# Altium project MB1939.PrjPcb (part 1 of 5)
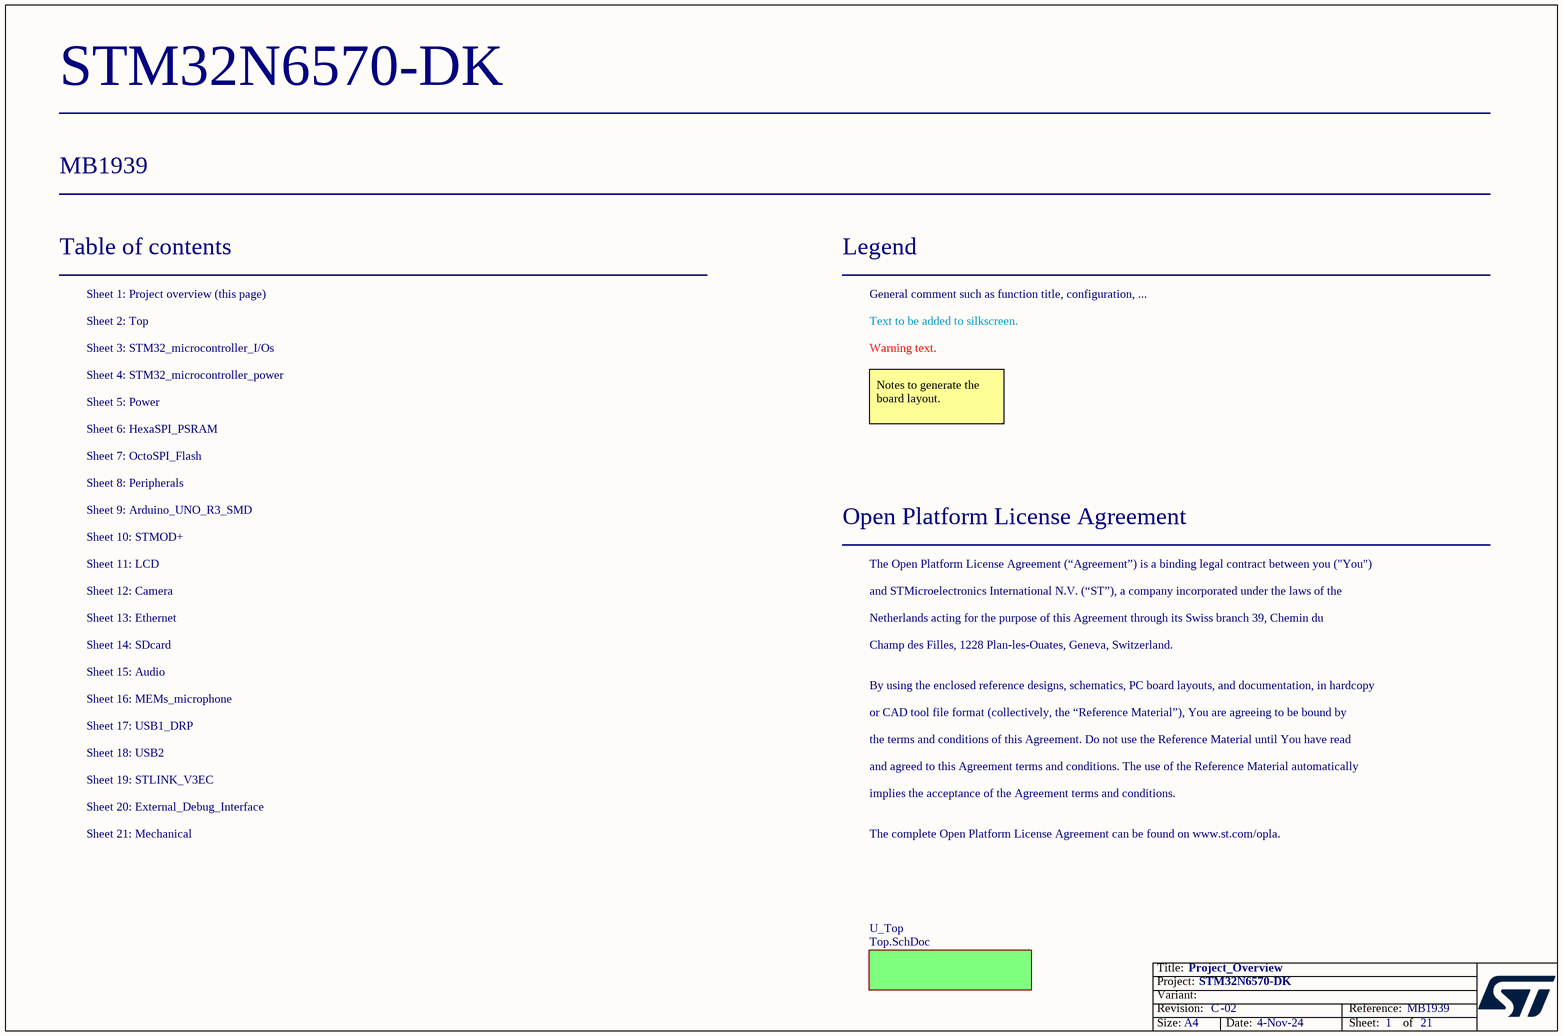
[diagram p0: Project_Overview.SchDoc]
Board_Reference: MB1939; Board_PCB_Revision: C; Board_Name: STM32N6570-DK; Board_Document_Date: 4-Nov-24; Board_Assembly_Revision: 02
21 sheets, 638 parts. Net scope: flat (ports and power ports of the same name join across sheets).
Board file: MB1939.PcbDoc
Sheets:
  Project_Overview.SchDoc
    U_Top = Top.SchDoc
      U_Arduino_UNO_R3_SMD = Arduino_UNO_R3_SMD.SchDoc
      U_Ethernet = Ethernet.SchDoc
      U_External_Debug_Interface = External_Debug_Interface.SchDoc
      U_HexaSPI_PSRAM = HexaSPI_PSRAM.SchDoc
      U_LCD = LCD.SchDoc
      U_Peripherals = Peripherals.SchDoc
      U_MEMs_microphone = MEMs_microphone.SchDoc
      U_OctoSPI_Flash = OctoSPI_Flash.SchDoc
      U_SDcard = SDcard.SchDoc
      U_STLINK_V3EC = STLINK_V3EC.SchDoc
      U_STMOD+ = STMOD+.SchDoc
      U_USB2 = USB2.SchDoc
      U_Mechanical = Mechanical.SchDoc
      U_STM32_microcontroller_power = STM32_microcontroller_power.SchDoc
      U_Audio_Codec = Audio_Codec.SchDoc
      U_USB1_DRP = USB1_DRP.SchDoc
      U_Camera = Camera.SchDoc
      U_Power = Power.SchDoc
      U_STM32_microcontroller_IOs = STM32_microcontroller_IOs.SchDoc

## Sheet Project_Overview.SchDoc: Project_Overview
size A4; Date: Not used; ApprovedBy: Not used; CheckedBy: Not used; Author: Not used; CompanyName: STMicroelectronics; DrawnBy: Not used; Engineer: Not used; Organization: Not used; Address1: Not used; Address2: Not used; Address3: Not used; Address4: Not used; DocumentNumber: Not used; Revision: Not used; SheetNumber: 1; SheetTotal: 21

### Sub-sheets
U_Top = Top.SchDoc: no entries

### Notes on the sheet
- Table of contents
- Sheet 1: Project overview (this page)
- Legend
- General comment such as function title, configuration, ...
- Sheet 2: Top
- Sheet 3: STM32_microcontroller_I/Os
- Sheet 4: STM32_microcontroller_power
- Text to be added to silkscreen.
- Warning text.
- Sheet 5: Power
- Sheet 6: HexaSPI_PSRAM
- Notes to generate the board layout.
- Sheet 7: OctoSPI_Flash
- Sheet 8: Peripherals
- Sheet 9: Arduino_UNO_R3_SMD
- Sheet 10: STMOD+
- Sheet 11: LCD
- Open Platform License Agreement
- The Open Platform License Agreement (“Agreement”) is a binding legal contract between you ("You")
- Sheet 12: Camera
- Sheet 13: Ethernet
- Sheet 14: SDcard
- and STMicroelectronics International N.V. (“ST”), a company incorporated under the laws of the
- Netherlands acting for the purpose of this Agreement through its Swiss branch 39, Chemin du
- Champ des Filles, 1228 Plan-les-Ouates, Geneva, Switzerland.
- Sheet 16: MEMs_microphone
- Sheet 15: Audio
- By using the enclosed reference designs, schematics, PC board layouts, and documentation, in hardcopy
- or CAD tool file format (collectively, the “Reference Material”), You are agreeing to be bound by
- Sheet 17: USB1_DRP
- Sheet 18: USB2
- Sheet 19: STLINK_V3EC
- the terms and conditions of this Agreement. Do not use the Reference Material until You have read
- and agreed to this Agreement terms and conditions. The use of the Reference Material automatically
- Sheet 20: External_Debug_Interface
- Sheet 21: Mechanical
- implies the acceptance of the Agreement terms and conditions.
- The complete Open Platform License Agreement can be found on www.st.com/opla.

## Sheet Top.SchDoc: Top
size A4; Date: Not used; ApprovedBy: Not used; CheckedBy: Not used; Author: Not used; CompanyName: STMicroelectronics; DrawnBy: Not used; Engineer: Not used; Organization: Not used; Address1: Not used; Address2: Not used; Address3: Not used; Address4: Not used; DocumentNumber: Not used; Revision: Not used; SheetNumber: 2; SheetTotal: 21
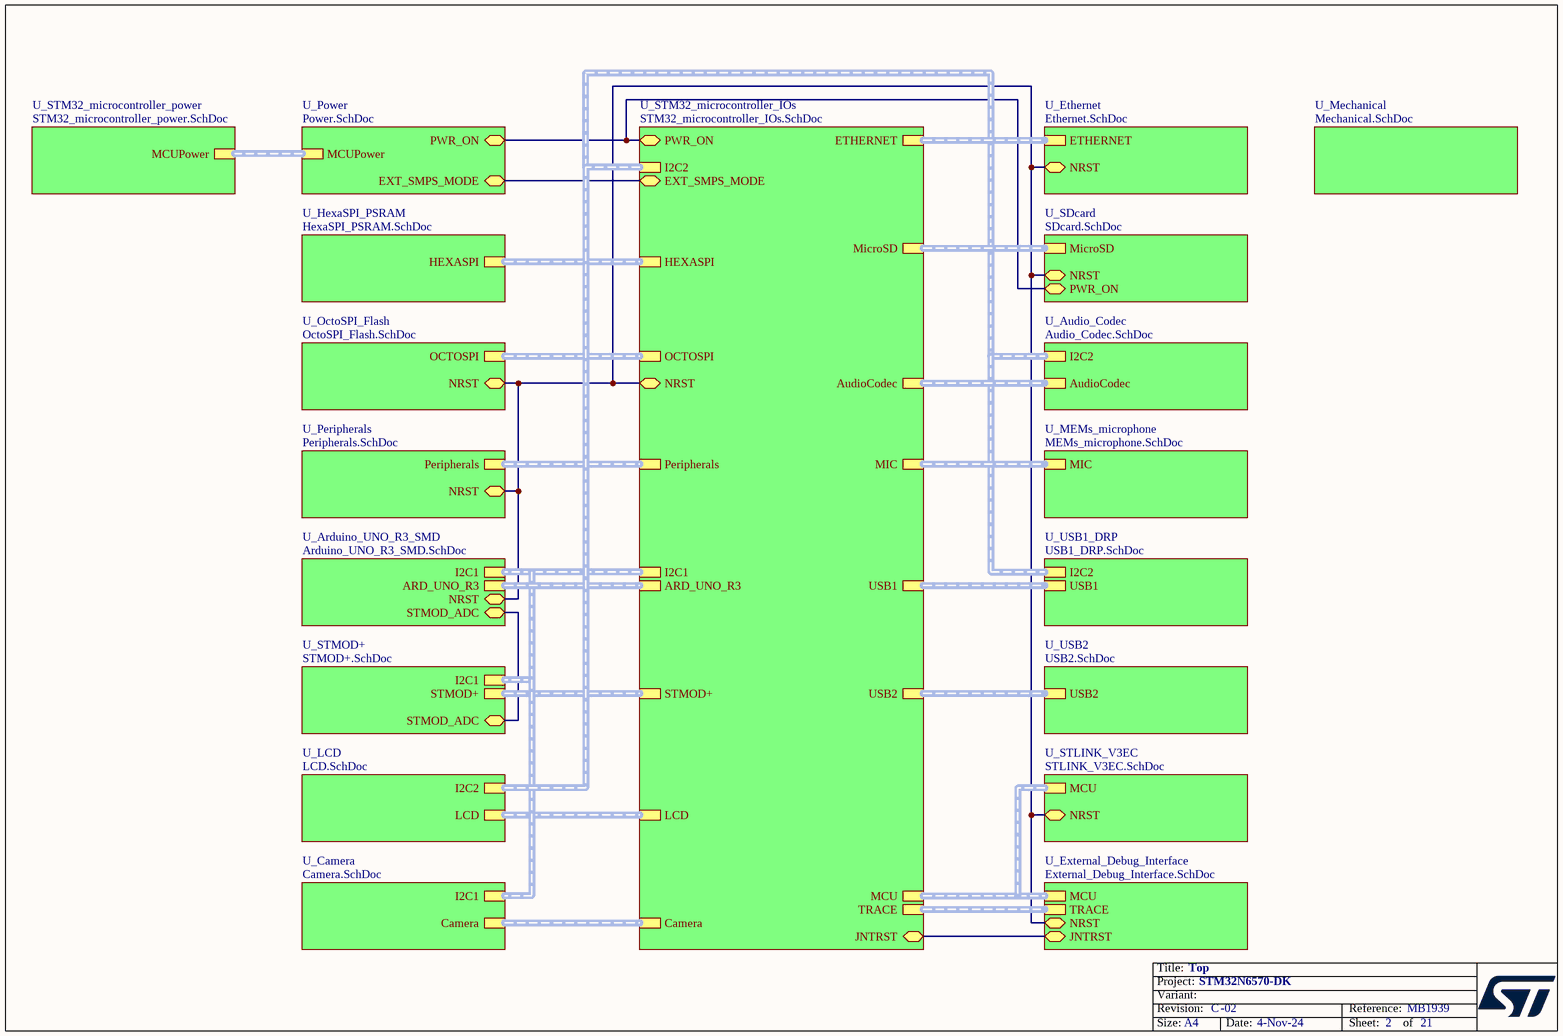
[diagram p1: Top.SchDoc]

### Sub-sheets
U_Arduino_UNO_R3_SMD = Arduino_UNO_R3_SMD.SchDoc: NRST (bidir), STMOD_ADC (bidir), I2C1 (harness I2C1), ARD_UNO_R3 (harness Arduino_UNO_R3)
U_Audio_Codec = Audio_Codec.SchDoc: I2C2 (harness I2C2), AudioCodec (harness AudioCodec)
U_Camera = Camera.SchDoc: Camera (harness Camera), I2C1 (harness I2C1)
U_Ethernet = Ethernet.SchDoc: NRST (bidir), ETHERNET (harness ETHERNET)
U_External_Debug_Interface = External_Debug_Interface.SchDoc: NRST (bidir), MCU (harness MCU), JNTRST (bidir), TRACE (harness TRACE)
U_HexaSPI_PSRAM = HexaSPI_PSRAM.SchDoc: HEXASPI (harness HEXASPI)
U_LCD = LCD.SchDoc: I2C2 (harness I2C2), LCD (harness LCD_RGB)
U_Mechanical = Mechanical.SchDoc: no entries
U_MEMs_microphone = MEMs_microphone.SchDoc: MIC (harness MIC)
U_OctoSPI_Flash = OctoSPI_Flash.SchDoc: NRST (bidir), OCTOSPI (harness OCTOSPI)
U_Peripherals = Peripherals.SchDoc: NRST (bidir), Peripherals (harness Peripherals)
U_Power = Power.SchDoc: PWR_ON (bidir), MCUPower (harness MCUPower), EXT_SMPS_MODE (bidir)
U_SDcard = SDcard.SchDoc: NRST (bidir), PWR_ON (bidir), MicroSD (harness MicroSD_SDIO)
U_STLINK_V3EC = STLINK_V3EC.SchDoc: NRST (bidir), MCU (harness MCU)
U_STM32_microcontroller_IOs = STM32_microcontroller_IOs.SchDoc: ARD_UNO_R3 (harness Arduino_UNO_R3), AudioCodec (harness AudioCodec), Camera (harness Camera), ETHERNET (harness ETHERNET), HEXASPI (harness HEXASPI), Peripherals (harness Peripherals), LCD (harness LCD_RGB), OCTOSPI (harness OCTOSPI), MicroSD (harness MicroSD_SDIO), STMOD+ (harness STMOD+), USB1 (harness USB1), USB2 (harness USB2), NRST (bidir), PWR_ON (bidir), JNTRST (bidir), TRACE (harness TRACE), MCU (harness MCU), I2C2 (harness I2C2), I2C1 (harness I2C1), MIC (harness MIC), EXT_SMPS_MODE (bidir)
U_STM32_microcontroller_power = STM32_microcontroller_power.SchDoc: MCUPower (harness MCUPower)
U_STMOD+ = STMOD+.SchDoc: STMOD_ADC (bidir), STMOD+ (harness STMOD+), I2C1 (harness I2C1)
U_USB1_DRP = USB1_DRP.SchDoc: USB1 (harness USB1), I2C2 (harness I2C2)
U_USB2 = USB2.SchDoc: USB2 (harness USB2)

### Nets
(unnamed): sheet U_Arduino_UNO_R3_SMD/NRST, sheet U_Ethernet/NRST, sheet U_External_Debug_Interface/NRST, sheet U_Peripherals/NRST, sheet U_OctoSPI_Flash/NRST, sheet U_SDcard/NRST, sheet U_STLINK_V3EC/NRST, sheet U_STM32_microcontroller_IOs/NRST
(unnamed): sheet U_Arduino_UNO_R3_SMD/STMOD_ADC, sheet U_STMOD+/STMOD_ADC  [a separate net that carries the same name]
(unnamed): sheet U_External_Debug_Interface/JNTRST, sheet U_STM32_microcontroller_IOs/JNTRST  [a separate net that carries the same name]
(unnamed): sheet U_SDcard/PWR_ON, sheet U_Power/PWR_ON, sheet U_STM32_microcontroller_IOs/PWR_ON  [a separate net that carries the same name]
(unnamed): sheet U_Power/EXT_SMPS_MODE, sheet U_STM32_microcontroller_IOs/EXT_SMPS_MODE  [a separate net that carries the same name]

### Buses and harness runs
harness sheet U_Arduino_UNO_R3_SMD/ARD_UNO_R3 = sheet U_STM32_microcontroller_IOs/ARD_UNO_R3
harness sheet U_Arduino_UNO_R3_SMD/I2C1 = sheet U_Camera/I2C1 = sheet U_STM32_microcontroller_IOs/I2C1 = sheet U_STMOD+/I2C1
harness sheet U_Audio_Codec/AudioCodec = sheet U_STM32_microcontroller_IOs/AudioCodec
harness sheet U_Audio_Codec/I2C2 = sheet U_LCD/I2C2 = sheet U_STM32_microcontroller_IOs/I2C2 = sheet U_USB1_DRP/I2C2
harness sheet U_Camera/Camera = sheet U_STM32_microcontroller_IOs/Camera
harness sheet U_Ethernet/ETHERNET = sheet U_STM32_microcontroller_IOs/ETHERNET
harness sheet U_External_Debug_Interface/MCU = sheet U_STLINK_V3EC/MCU = sheet U_STM32_microcontroller_IOs/MCU
harness sheet U_External_Debug_Interface/TRACE = sheet U_STM32_microcontroller_IOs/TRACE
harness sheet U_HexaSPI_PSRAM/HEXASPI = sheet U_STM32_microcontroller_IOs/HEXASPI
harness sheet U_LCD/LCD = sheet U_STM32_microcontroller_IOs/LCD
harness sheet U_MEMs_microphone/MIC = sheet U_STM32_microcontroller_IOs/MIC
harness sheet U_OctoSPI_Flash/OCTOSPI = sheet U_STM32_microcontroller_IOs/OCTOSPI
harness sheet U_Peripherals/Peripherals = sheet U_STM32_microcontroller_IOs/Peripherals
harness sheet U_Power/MCUPower = sheet U_STM32_microcontroller_power/MCUPower
harness sheet U_SDcard/MicroSD = sheet U_STM32_microcontroller_IOs/MicroSD
harness sheet U_STM32_microcontroller_IOs/STMOD+ = sheet U_STMOD+/STMOD+
harness sheet U_STM32_microcontroller_IOs/USB1 = sheet U_USB1_DRP/USB1
harness sheet U_STM32_microcontroller_IOs/USB2 = sheet U_USB2/USB2

## Sheet Arduino_UNO_R3_SMD.SchDoc: Schematic sheet title to update
size A3; Date: Not used; ApprovedBy: Not used; CheckedBy: Not used; Author: Not used; CompanyName: STMicroelectronics; DrawnBy: Not used; Engineer: Not used; Organization: Not used; Address1: Not used; Address2: Not used; Address3: Not used; Address4: Not used; DocumentNumber: Not used; Revision: 0.4; SheetNumber: 9; SheetTotal: 21
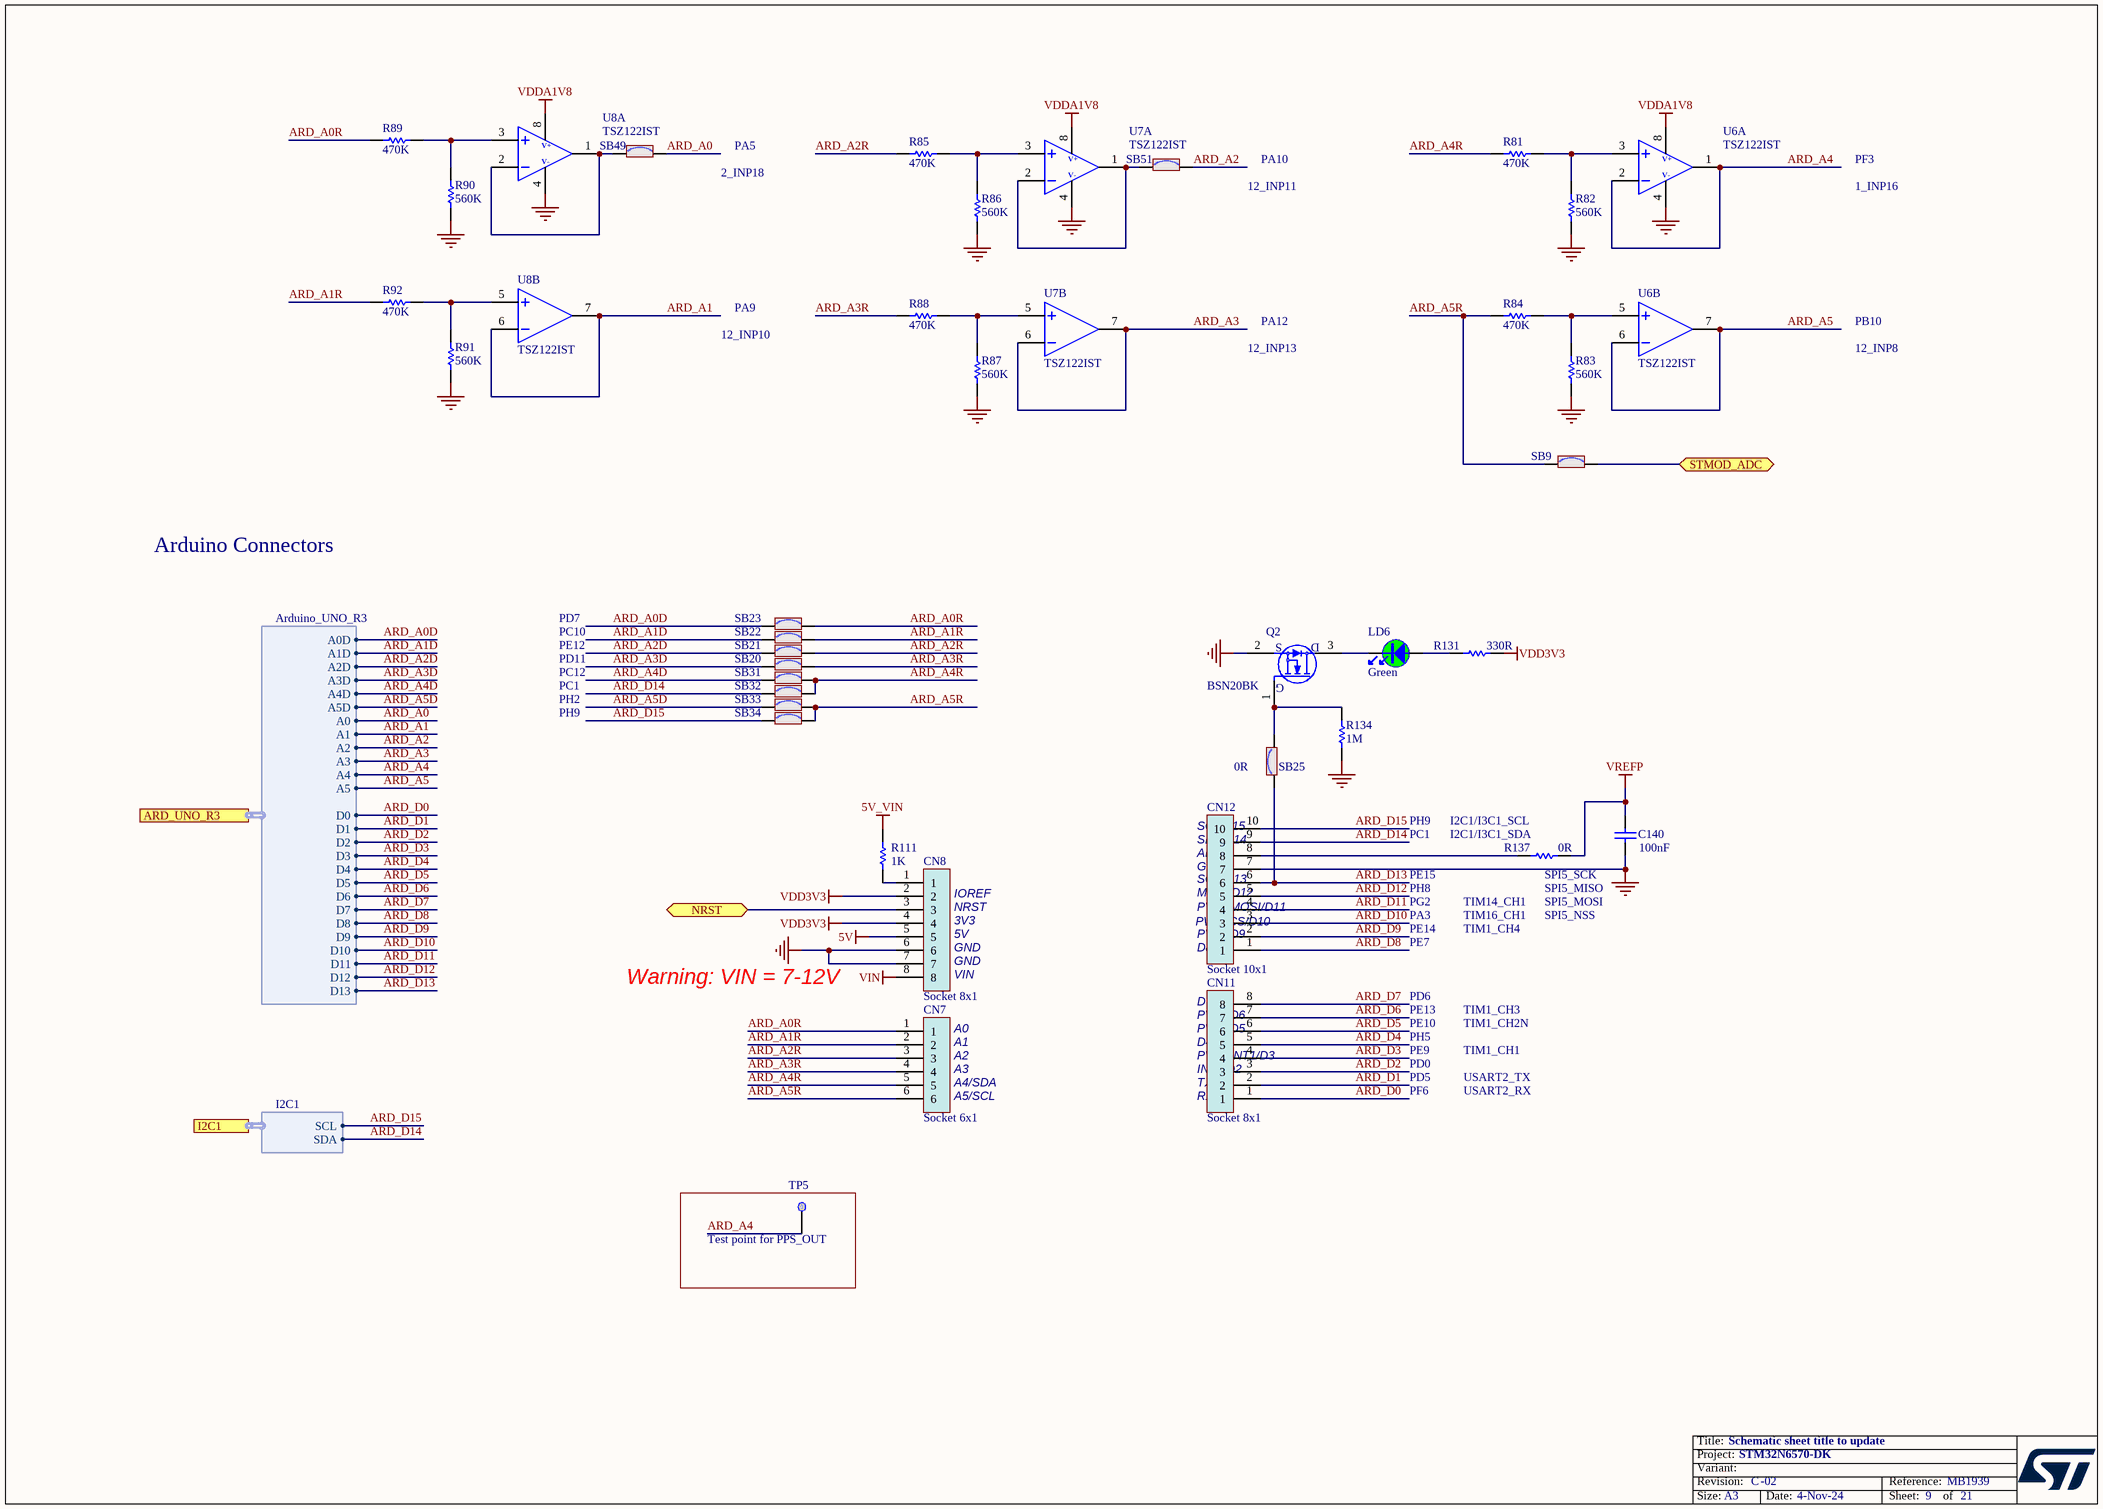
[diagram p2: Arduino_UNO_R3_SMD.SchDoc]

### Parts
C140  value 100nF  [C0402]  (hidden comment: Capacitor)
CN7  Socket 6x1  [CON_SAMTEC_SSW-106-22-X-S-VS]
CN8  Socket 8x1  [CON_SAMTEC_SSW-108-22-X-S-VS]
CN11  Socket 8x1  [CON_SAMTEC_SSW-108-22-X-S-VS]
CN12  Socket 10x1  [CON_SAMTEC_SSW-110-22-X-S-VS]
LD6  value Green  [LED_0603_OSRAM_LG-Q396-PS-35_GREEN_1A2K_H0P4]  (hidden comment: LED_green)
Q2  value BSN20BK  [MOS_SOT23]  (hidden comment: BSN20)
R81  value 470K  [R0402]  (hidden comment: Resistor)
R82  value 560K  [R0402]  (hidden comment: Resistor)
R83  value 560K  [R0402]  (hidden comment: Resistor)
R84  value 470K  [R0402]  (hidden comment: Resistor)
R85  value 470K  [R0402]  (hidden comment: Resistor)
R86  value 560K  [R0402]  (hidden comment: Resistor)
R87  value 560K  [R0402]  (hidden comment: Resistor)
R88  value 470K  [R0402]  (hidden comment: Resistor)
R89  value 470K  [R0402]  (hidden comment: Resistor)
R90  value 560K  [R0402]  (hidden comment: Resistor)
R91  value 560K  [R0402]  (hidden comment: Resistor)
R92  value 470K  [R0402]  (hidden comment: Resistor)
R111  value 1K  [R0402]  (hidden comment: Resistor)
R131  value 330R  [R0402]  (hidden comment: Resistor)
R134  value 1M  [R0402]  (hidden comment: Resistor)
R137  value 0R  [R0402]  (hidden comment: Resistor)
SB9  SB_ON  [SOLDER-BRIDGE_R0603-0R]  (value not drawn)
SB20  SB_ON  [SOLDER-BRIDGE_R0603-0R]  (value not drawn)
SB21  SB_ON  [SOLDER-BRIDGE_R0603-0R]  (value not drawn)
SB22  SB_ON  [SOLDER-BRIDGE_R0603-0R]  (value not drawn)
SB23  SB_ON  [SOLDER-BRIDGE_R0603-0R]  (value not drawn)
SB25  value 0R  [SOLDER-BRIDGE_R0603-0R]  (hidden comment: SB_ON)
SB31  SB_ON  [SOLDER-BRIDGE_R0603-0R]  (value not drawn)
SB32  SB_ON  [SOLDER-BRIDGE_R0603-0R]  (value not drawn)
SB33  SB_ON  [SOLDER-BRIDGE_R0603-0R]  (value not drawn)
SB34  SB_ON  [SOLDER-BRIDGE_R0603-0R]  (value not drawn)
SB49  SB_ON  [SOLDER-BRIDGE_R0603-0R]  (value not drawn)
SB51  SB_ON  [SOLDER-BRIDGE_R0603-0R]  (value not drawn)
TP5  Test Point  [TP_SMD_2MM]  (value not drawn)  (no BOM)
U6  TSZ122IST  [ICC_MINISO8_3X3_P065]  (parts A,B of 2)
U7  TSZ122IST  [ICC_MINISO8_3X3_P065]  (parts A,B of 2)
U8  TSZ122IST  [ICC_MINISO8_3X3_P065]  (parts A,B of 2)

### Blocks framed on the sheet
Test point for PPS_OUT: TP5

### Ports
ARD_UNO_R3 (harness Arduino_UNO_R3), I2C1 (harness I2C1), NRST (bidir), STMOD_ADC (bidir)

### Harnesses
I2C1: SCL, SDA
Arduino_UNO_R3: A0, A1, A2, A3, A4, A5, D0, D1, D2, D3, D4, D5, D6, D7, D8, D9, D10, D11, D12, D13, A0D, A1D, A2D, A3D, A4D, A5D

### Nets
5V: CN8.5
5V_VIN: R111.2
GND: C140.2 CN8.6 CN8.7 CN12.7 Q2.2(S) R82.1 R83.1 R86.1 R87.1 R90.1 R91.1 R134.1 U6.4 U7.4 U8.4
VDD3V3: CN8.2 CN8.4 R131.2
VDDA1V8: U6.8 U7.8 U8.8
VIN: CN8.8
VREFP: C140.1 R137.2
ARD_A0: SB49.2 ; port ARD_UNO_R3.A0
ARD_A0D: SB23.1 ; port ARD_UNO_R3.A0D
ARD_A0R: CN7.1 R89.1 SB23.2
ARD_A1: U8.6 U8.7 ; port ARD_UNO_R3.A1
ARD_A1D: SB22.1 ; port ARD_UNO_R3.A1D
ARD_A1R: CN7.2 R92.1 SB22.2
ARD_A2: SB51.2 ; port ARD_UNO_R3.A2
ARD_A2D: SB21.1 ; port ARD_UNO_R3.A2D
ARD_A2R: CN7.3 R85.1 SB21.2
ARD_A3: U7.6 U7.7 ; port ARD_UNO_R3.A3
ARD_A3D: SB20.1 ; port ARD_UNO_R3.A3D
ARD_A3R: CN7.4 R88.1 SB20.2
ARD_A4: TP5.1 U6.1 U6.2 ; port ARD_UNO_R3.A4
ARD_A4D: SB31.1 ; port ARD_UNO_R3.A4D
ARD_A4R: CN7.5 R81.1 SB31.2 SB32.2
ARD_A5: U6.6 U6.7 ; port ARD_UNO_R3.A5
ARD_A5D: SB33.1 ; port ARD_UNO_R3.A5D
ARD_A5R: CN7.6 R84.1 SB9.1 SB33.2 SB34.2
ARD_D0: CN11.1 ; port ARD_UNO_R3.D0
ARD_D1: CN11.2 ; port ARD_UNO_R3.D1
ARD_D2: CN11.3 ; port ARD_UNO_R3.D2
ARD_D3: CN11.4 ; port ARD_UNO_R3.D3
ARD_D4: CN11.5 ; port ARD_UNO_R3.D4
ARD_D5: CN11.6 ; port ARD_UNO_R3.D5
ARD_D6: CN11.7 ; port ARD_UNO_R3.D6
ARD_D7: CN11.8 ; port ARD_UNO_R3.D7
ARD_D8: CN12.1 ; port ARD_UNO_R3.D8
ARD_D9: CN12.2 ; port ARD_UNO_R3.D9
ARD_D10: CN12.3 ; port ARD_UNO_R3.D10
ARD_D11: CN12.4 ; port ARD_UNO_R3.D11
ARD_D12: CN12.5 ; port ARD_UNO_R3.D12
ARD_D13: CN12.6 SB25.1 ; port ARD_UNO_R3.D13
ARD_D14: CN12.9 SB32.1 ; port I2C1.SDA
ARD_D15: CN12.10 SB34.1 ; port I2C1.SCL
NRST: CN8.3 ; port NRST
STMOD_ADC: SB9.2 ; port STMOD_ADC
NetCN8_1: CN8.1 R111.1
NetCN12_8: CN12.8 R137.1
NetLD6_1: LD6.1 R131.1
NetLD6_2: LD6.2 Q2.3(D)
NetQ2_1: Q2.1(G) R134.2 SB25.2
NetR81_2: R81.2 R82.2 U6.3
NetR83_2: R83.2 R84.2 U6.5
NetR85_2: R85.2 R86.2 U7.3
NetR87_2: R87.2 R88.2 U7.5
NetR89_2: R89.2 R90.2 U8.3
NetR91_2: R91.2 R92.2 U8.5
NetSB49_1: SB49.1 U8.1 U8.2
NetSB51_1: SB51.1 U7.1 U7.2

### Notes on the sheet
- 2_INP18
- PA5
- PA10
- PF3
- 12_INP11
- 1_INP16
- PA9
- 12_INP10
- 12_INP13
- PA12
- PB10
- 12_INP8
- Arduino Connectors
- PC10
- PE12
- PD7
- PD11
- PC12
- PH2
- PH9
- PC1
- (near CN12) SDA/D14
- (near CN12) SCL/D15
- (near CN12) AREF
- (near R137) I2C1/I3C1_SCL
- (near R137) I2C1/I3C1_SDA
- (near CN8) IOREF
- (near CN8) NRST
- (near CN8) 3V3
- (near CN12) PWM/CS/D10
- (near CN12) SCK/D13
- (near CN12) MISO/D12
- (near CN12) GND
- (near CN12) PWM/MOSI/D11
- PG2
- PH8
- PE15
- PA3
- TIM16_CH1
- (near R137) TIM14_CH1
- SPI5_NSS
- (near R137) SPI5_SCK
- SPI5_MOSI
- (near R137) SPI5_MISO
- Warning: VIN = 7-12V
- (near CN8) 5V
- (near CN8) GND
- (near CN8) VIN
- (near CN12) D8
- (near CN12) PWM/D9
- PE7
- PE14
- TIM1_CH4
- (near CN7) A0
- (near CN7) A1
- (near CN7) A2
- (near CN11) D4
- (near CN11) PWM/INT1/D3
- (near CN11) PWM/D5
- (near CN11) PWM/D6
- D7
- PE9
- PE10
- PH5
- PD6
- PE13
- TIM1_CH1
- TIM1_CH2N
- TIM1_CH3
- (near CN7) A3
- (near CN7) A4/SDA
- (near CN7) A5/SCL
- (near CN11) RX/D0
- (near CN11) TX/D1
- (near CN11) INT0/D2
- PD5
- PD0
- PF6
- USART2_RX
- USART2_TX

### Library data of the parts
C140 = MCD-00006: Capacitor, MLCC, 100nF, 16V, X7R, +/-10%, 0402, T=0.5mm; Manufacturer_Part_Number: CC0402KRX7R7BB104; Manufacturer: YAGEO; Part_Preference: Recommended; Partial_Alternate_Internal_Part_Number: MCD-03299; Order_Code_RS: 9402047; Component_Country_Of_Origin: China; ShowFields: YES; ID: 2474
CN7 = MCD-00299: Socket, 6x1, 2.54mm, VR, SMD, T=9.78mm; Part_Type: Connector; Part_Preference: Recommended; Manufacturer: SAMTEC; Manufacturer_Part_Number: SSW-106-22-L-S-VS; Component_Country_Of_Origin: China, Costa Rica, Malaysia, USA, Vietnam; ShowFields: YES; ID: 2569
CN8 CN11 = MCD-00300: Socket, 8x1, 2.54mm, VR, SMD, T=9.78mm; Part_Type: Connector; Part_Preference: Recommended; Manufacturer: SAMTEC; Manufacturer_Part_Number: SSW-108-22-L-S-VS; Component_Country_Of_Origin: China, Costa Rica, Malaysia, USA, Vietnam; ShowFields: YES; ID: 2571
CN12 = MCD-00301: Socket, 10x1, 2.54mm, VR, SMD, T=9.78mm; Part_Type: Connector; Part_Preference: Recommended; Manufacturer: SAMTEC; Manufacturer_Part_Number: SSW-110-22-L-S-VS; Component_Country_Of_Origin: China, Costa Rica, Malaysia, USA, Vietnam; ShowFields: YES; ID: 2566
LD6 = MCD-00588: LED, Green, 2V, 20mA, 0603; Part_Type: Display; Manufacturer_Part_Number: LG Q396-PS-35; Manufacturer: OSRAM OPTO SEMICONDUCTORS; Part_Preference: Recommended; Partial_Alternate_Internal_Part_Number: MCD-02400, MCD-03155, MCD-02901; Component_Country_Of_Origin: Unknown; ShowFields: YES; ID: 3155
Q2 = MCD-01969: Transistor, MOSFET, N-CH, 60V, 265mA, SOT23-3; Part_Preference: Recommended; Manufacturer: NEXPERIA; Order_Code_RS: 136-4845; Component_Country_Of_Origin: China; ShowFields: YES; ID: 4069
R81 R84 R85 R88 R89 R92 = MCD-00483: Resistor, 470K, 0402, +/-1%, 1/16W; Part_Preference: Recommended; Manufacturer: YAGEO; Manufacturer_Part_Number: RC0402FR-07470KL; Component_Country_Of_Origin: China; ShowFields: YES; ID: 2797
R82 R83 R86 R87 R90 R91 = MCD-00495: Resistor, 560K, 0402, +/-1%, 1/16W; Part_Preference: Recommended; Manufacturer: YAGEO; Manufacturer_Part_Number: RC0402FR-07560KL; Component_Country_Of_Origin: China; ShowFields: YES; ID: 2779
R111 = MCD-00061: Resistor, 1K, 0402, +/-1%,1/16W; Manufacturer_Part_Number: RC0402FR-071KL; Manufacturer: YAGEO; Part_Preference: Recommended; Order_Code_RS: 9239235; Component_Country_Of_Origin: China; ShowFields: YES; ID: 2532
R131 = MCD-00062: Resistor, 330R, 0402, +/-1%, 1/16W; Manufacturer_Part_Number: RC0402FR-07330RL; Manufacturer: YAGEO; Part_Preference: Recommended; Order_Code_RS: 9239170; Component_Country_Of_Origin: China; ShowFields: YES; ID: 2529
R134 = MCD-00182: Resistor, 1M, 0402, +/-1%, 1/16W; Manufacturer_Part_Number: RC0402FR-071ML; Manufacturer: YAGEO; BMS_Part_Number: 9131778; Part_Preference: Recommended; Order_Code_RS: 618-6194; Component_Country_Of_Origin: China; ShowFields: YES; ID: 2686
R137 = MCD-00052: Resistor, 0R, 0402, +/-5%, 1/16W; Manufacturer_Part_Number: RC0402JR-070RL; Manufacturer: YAGEO; Part_Preference: Recommended; Order_Code_RS: 9232516RL; Component_Country_Of_Origin: China; ShowFields: YES; ID: 2540
SB9 SB20-SB23 SB25 SB31-SB34 SB49 SB51 = MCD-00071: Resistor, 0R, SB0603, 5%, 0.1W; Manufacturer_Part_Number: RC0603JR-070RL; Manufacturer: YAGEO; Part_Preference: Recommended; Manufacturer_HQ_COO: Unknown; ShowFields: YES; ID: 2521; Order_Code_RS: 199-5647; Component_Country_Of_Origin: China
TP5 = MCD-00177: Test Point, SMD, 2mm; Part_Type: Misc; Part_Preference: Recommended; ShowFields: YES; ID: 2690; Component_Country_Of_Origin: Unknown
U6-U8 = MCD-00325: Operational Amplifier, Single/dual/quad rail-to-rail input/output, 5V5, 400KHz; BMS_Part_Number: 9177443; Part_Type: IC; Part_Preference: Recommended; Manufacturer: STMICROELECTRONICS; Manufacturer_HQ_COO: EU; Component_Country_Of_Origin: Philippines; ShowFields: YES; ID: 2953

## Sheet Ethernet.SchDoc: Ethernet
size A4; Date: 01-DEC-2013; CompanyName: STMicroelectronics; Organization: Microcontrollers Division; Address1: 12, Rue Jules HOROWITZ; Address2: 38019 Grenoble; Address3: FRANCE; DocumentNumber: MB1272; Revision: A-01; SheetNumber: 13; SheetTotal: 21; Project: STM32MP15-DISCO PI
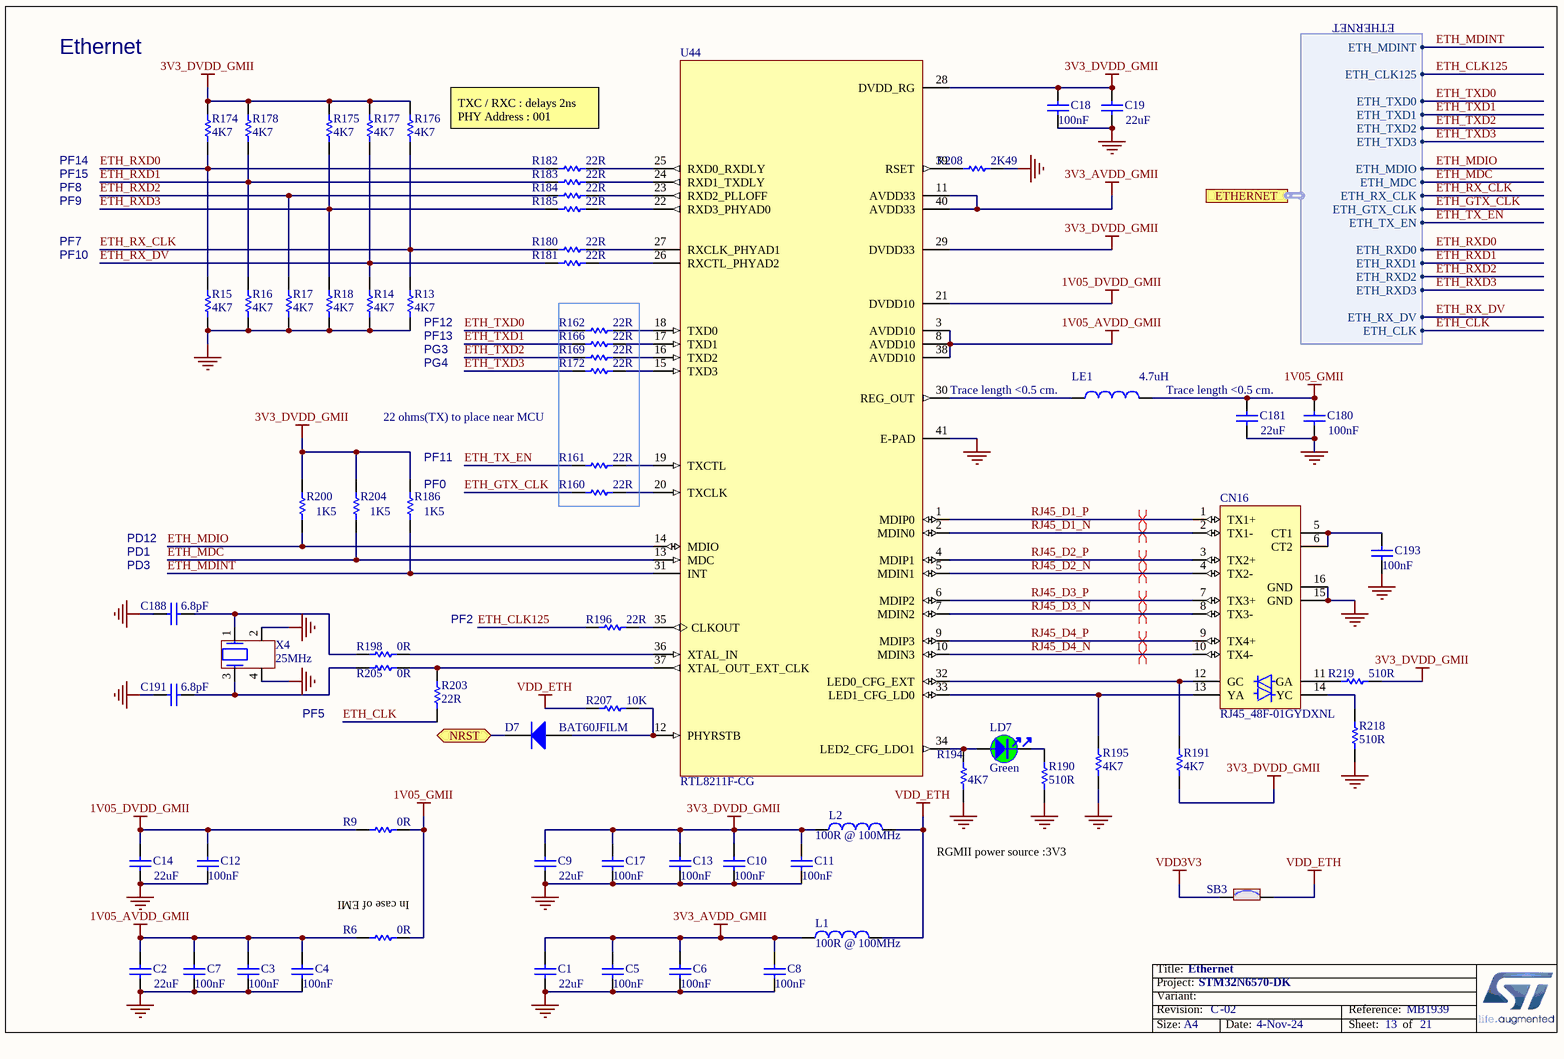
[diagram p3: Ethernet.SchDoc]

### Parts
C1  value 22uF  [C0603]  (hidden comment: Capacitor)
C2  value 22uF  [C0603]  (hidden comment: Capacitor)
C3  value 100nF  [C0402]  (hidden comment: Capacitor)
C4  value 100nF  [C0402]  (hidden comment: Capacitor)
C5  value 100nF  [C0402]  (hidden comment: Capacitor)
C6  value 100nF  [C0402]  (hidden comment: Capacitor)
C7  value 100nF  [C0402]  (hidden comment: Capacitor)
C8  value 100nF  [C0402]  (hidden comment: Capacitor)
C9  value 22uF  [C0603]  (hidden comment: Capacitor)
C10  value 100nF  [C0402]  (hidden comment: Capacitor)
C11  value 100nF  [C0402]  (hidden comment: Capacitor)
C12  value 100nF  [C0402]  (hidden comment: Capacitor)
C13  value 100nF  [C0402]  (hidden comment: Capacitor)
C14  value 22uF  [C0603]  (hidden comment: Capacitor)
C17  value 100nF  [C0402]  (hidden comment: Capacitor)
C18  value 100nF  [C0402]  (hidden comment: Capacitor)
C19  value 22uF  [C0603]  (hidden comment: Capacitor)
C180  value 100nF  [C0402]  (hidden comment: Capacitor)
C181  value 22uF  [C0603]  (hidden comment: Capacitor)
C188  value 6.8pF  [C0402]  (hidden comment: Capacitor)
C191  value 6.8pF  [C0402]  (hidden comment: Capacitor)
C193  value 100nF  [C0402]  (hidden comment: Capacitor)
CN16  value RJ45_48F-01GYDXNL  [CON_RJ45_YD_48F-01GYDXNL_LED-P]  (hidden comment: ​New part for use of led pulled down on pin 13/14 , schematic more lisible.)
D7  BAT60JFILM  [DIO_SOD323]
L1  value 100R @ 100MHz  [FIL_0603_H0P65]  (hidden comment: BEAD)
L2  value 100R @ 100MHz  [FIL_0603_H0P65]  (hidden comment: BEAD)
LD7  value Green  [LED_0603_OSRAM_LG-Q396-PS-35_GREEN_1A2K_H0P4]  (hidden comment: LED_green)
LE1  value 4.7uH  [L1210_LQH]  (hidden comment: Inductor)
R6  value 0R  [R0603]  (hidden comment: Resistor)
R9  value 0R  [R0603]  (hidden comment: Resistor)
R13  value 4K7  [R0402]  (hidden comment: Resistor)
R14  value 4K7  [R0402]  (hidden comment: Resistor)
R15  value 4K7  [R0402]  (hidden comment: Resistor)
R16  value 4K7  [R0402]  (hidden comment: Resistor)
R17  value 4K7  [R0402]  (hidden comment: Resistor)
R18  value 4K7  [R0402]  (hidden comment: Resistor)
R160  value 22R  [R0402]  (hidden comment: Resistor)
R161  value 22R  [R0402]  (hidden comment: Resistor)
R162  value 22R  [R0402]  (hidden comment: Resistor)
R166  value 22R  [R0402]  (hidden comment: Resistor)
R169  value 22R  [R0402]  (hidden comment: Resistor)
R172  value 22R  [R0402]  (hidden comment: Resistor)
R174  value 4K7  [R0402]  (hidden comment: Resistor)
R175  value 4K7  [R0402]  (hidden comment: Resistor)
R176  value 4K7  [R0402]  (hidden comment: Resistor)
R177  value 4K7  [R0402]  (hidden comment: Resistor)
R178  value 4K7  [R0402]  (hidden comment: Resistor)
R180  value 22R  [R0402]  (hidden comment: Resistor)
R181  value 22R  [R0402]  (hidden comment: Resistor)
R182  value 22R  [R0402]  (hidden comment: Resistor)
R183  value 22R  [R0402]  (hidden comment: Resistor)
R184  value 22R  [R0402]  (hidden comment: Resistor)
R185  value 22R  [R0402]  (hidden comment: Resistor)
R186  value 1K5  [R0402]  (hidden comment: Resistor)
R190  value 510R  [R0402]  (hidden comment: Resistor)
R191  value 4K7  [R0402]  (hidden comment: Resistor)
R194  value 4K7  [R0402]  (hidden comment: Resistor)
R195  value 4K7  [R0402]  (hidden comment: Resistor)
R196  value 22R  [R0402]  (hidden comment: Resistor)
R198  value 0R  [R0402]  (hidden comment: Resistor)
R200  value 1K5  [R0402]  (hidden comment: Resistor)
R203  value 22R  [R0402]  (hidden comment: Resistor)
R204  value 1K5  [R0402]  (hidden comment: Resistor)
R205  value 0R  [R0402]  (hidden comment: Resistor)
R207  value 10K  [R0402]  (hidden comment: Resistor)
R208  value 2K49  [R0402]  (hidden comment: Resistor)
R218  value 510R  [R0402]  (hidden comment: Resistor)
R219  value 510R  [R0402]  (hidden comment: Resistor)
SB3  SB_ON  [SOLDER-BRIDGE_R0402-0R]  (value not drawn)
U44  RTL8211F-CG  [ICC_QFN40-EPAD_5X5_P040]
X4  value 25MHz  [CRY_NX3225HA_4P]  (hidden comment: XTAL_4_PINS)

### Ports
ETHERNET (harness ETHERNET), NRST (bidir)

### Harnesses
ETHERNET: ETH_MDINT, ETH_CLK125, ETH_TXD0, ETH_MDIO, ETH_MDC, ETH_RX_CLK, ETH_GTX_CLK, ETH_TX_EN, ETH_RXD0, ETH_RX_DV, ETH_CLK, ETH_TXD1, ETH_TXD2, ETH_TXD3, ETH_RXD1, ETH_RXD2, ETH_RXD3

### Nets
1V05_AVDD_GMII: C2.2 C3.2 C4.2 C7.2 R6.1 U44.3(AVDD10) U44.8(AVDD10) U44.38(AVDD10)
1V05_DVDD_GMII: C12.2 C14.2 R9.1 U44.21(DVDD10)
1V05_GMII: C180.2 C181.2 LE1.2 R6.2 R9.2
3V3_AVDD_GMII: C1.2 C5.2 C6.2 C8.2 L1.1 U44.11(AVDD33) U44.40(AVDD33)
3V3_DVDD_GMII: C9.2 C10.2 C11.2 C13.2 C17.2 C18.2 C19.1 L2.1 R174.2 R175.2 R176.2 R177.2 R178.2 R186.2 R191.1 R200.2 R204.2 R219.2 U44.28(DVDD_RG) U44.29(DVDD33)
GND: C1.1 C2.1 C3.1 C4.1 C5.1 C6.1 C7.1 C8.1 C9.1 C10.1 C11.1 C12.1 C13.1 C14.1 C17.1 C18.1 C19.2 C180.1 C181.1 C188.1 C191.1 C193.1 CN16.15(GND) CN16.16(GND) R13.1 R14.1 R15.1 R16.1 R17.1 R18.1 R190.1 R194.1 R195.1 R208.2 R218.1 U44.41(E-PAD) X4.2 X4.4
VDD3V3: SB3.1
VDD_ETH: L1.2 L2.2 R207.1 SB3.2
ETH_CLK: R203.2 ; port ETHERNET.ETH_CLK
ETH_CLK125: R196.1 ; port ETHERNET.ETH_CLK125
ETH_GTX_CLK: R160.1 ; port ETHERNET.ETH_GTX_CLK
ETH_MDC: R204.1 U44.13(MDC) ; port ETHERNET.ETH_MDC
ETH_MDINT: R186.1 U44.31(INT) ; port ETHERNET.ETH_MDINT
ETH_MDIO: R200.1 U44.14(MDIO) ; port ETHERNET.ETH_MDIO
ETH_RX_CLK: R13.2 R176.1 R180.1 ; port ETHERNET.ETH_RX_CLK
ETH_RX_DV: R14.2 R177.1 R181.1 ; port ETHERNET.ETH_RX_DV
ETH_RXD0: R15.2 R174.1 R182.1 ; port ETHERNET.ETH_RXD0
ETH_RXD1: R16.2 R178.1 R183.1 ; port ETHERNET.ETH_RXD1
ETH_RXD2: R17.2 R184.1 ; port ETHERNET.ETH_RXD2
ETH_RXD3: R18.2 R175.1 R185.1 ; port ETHERNET.ETH_RXD3
ETH_TX_EN: R161.1 ; port ETHERNET.ETH_TX_EN
ETH_TXD0: R162.1 ; port ETHERNET.ETH_TXD0
ETH_TXD1: R166.1 ; port ETHERNET.ETH_TXD1
ETH_TXD2: R169.1 ; port ETHERNET.ETH_TXD2
ETH_TXD3: R172.1 ; port ETHERNET.ETH_TXD3
NRST: D7.2(K) ; port NRST
RJ45_D1_N: CN16.2(TX1-) U44.2(MDIN0)
RJ45_D1_P: CN16.1(TX1+) U44.1(MDIP0)
RJ45_D2_N: CN16.4(TX2-) U44.5(MDIN1)
RJ45_D2_P: CN16.3(TX2+) U44.4(MDIP1)
RJ45_D3_N: CN16.8(TX3-) U44.7(MDIN2)
RJ45_D3_P: CN16.7(TX3+) U44.6(MDIP2)
RJ45_D4_N: CN16.10(TX4-) U44.10(MDIN3)
RJ45_D4_P: CN16.9(TX4+) U44.9(MDIP3)
NetC188_2: C188.2 R198.1 X4.1
NetC191_2: C191.2 R205.1 X4.3
NetC193_2: C193.2 CN16.5(CT1) CN16.6(CT2)
NetCN16_11: CN16.11(GA) R219.1
NetCN16_12: CN16.12(GC) R191.2 U44.32(LED0_CFG_EXT)
NetCN16_13: CN16.13(YA) R195.2 U44.33(LED1_CFG_LD0)
NetCN16_14: CN16.14(YC) R218.2
NetD7_1: D7.1(A) R207.2 U44.12(PHYRSTB)
NetLD7_1: LD7.1 R194.2 U44.34(LED2_CFG_LDO1)
NetLD7_2: LD7.2 R190.2
NetLE1_1: LE1.1 U44.30(REG_OUT)
NetR160_2: R160.2 U44.20(TXCLK)
NetR161_2: R161.2 U44.19(TXCTL)
NetR162_2: R162.2 U44.18(TXD0)
NetR166_2: R166.2 U44.17(TXD1)
NetR169_2: R169.2 U44.16(TXD2)
NetR172_2: R172.2 U44.15(TXD3)
NetR180_2: R180.2 U44.27(RXCLK_PHYAD1)
NetR181_2: R181.2 U44.26(RXCTL_PHYAD2)
NetR182_2: R182.2 U44.25(RXD0_RXDLY)
NetR183_2: R183.2 U44.24(RXD1_TXDLY)
NetR184_2: R184.2 U44.23(RXD2_PLLOFF)
NetR185_2: R185.2 U44.22(RXD3_PHYAD0)
NetR196_2: R196.2 U44.35(CLKOUT)
NetR198_2: R198.2 U44.36(XTAL_IN)
NetR203_1: R203.1 R205.2 U44.37(XTAL_OUT_EXT_CLK)
NetR208_1: R208.1 U44.39(RSET)

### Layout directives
differential pair: RJ45_D1_N, RJ45_D1_P, RJ45_D2_N, RJ45_D2_P, RJ45_D3_N, RJ45_D3_P, RJ45_D4_N, RJ45_D4_P

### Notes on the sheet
- Ethernet
- PF15
- PF14
- TXC / RXC : delays 2ns
  PHY Address : 001
- PF9
- PF8
- PF7
- PF10
- (near R13) PF12
- (near R13) PF13
- (near R13) PG3
- PG4
- 22 ohms(TX) to place near MCU
- (near LE1) Trace length <0.5 cm.
- (near C181) Trace length <0.5 cm.
- (near R186) PF0
- (near R186) PF11
- PD12
- PD1
- (near C188) PD3
- PF2
- PF5
- (near R6) In case of EMI
- RGMII power source :3V3

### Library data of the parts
C1 C2 C9 C14 C19 C181 = MCD-00100: Capacitor, MLCC, 22uF, 6V3, X5R, +/-20%, 0603, T=0.8mm; Manufacturer_Part_Number: GRM188R60J226MEA0J; Manufacturer: MURATA; Part_Preference: Recommended; Component_Country_Of_Origin: Japan°°; ShowFields: YES; ID: 2766
C3-C8 C10-C13 C17 C18 C180 C193 = MCD-00006: as C140 on sheet Arduino_UNO_R3_SMD
C188 C191 = MCD-01781: Capacitor, MLCC, 6.8pF, 50V, NPO, +/-0.1pF, 0402, T=0.5mm; Part_Preference: Recommended; Manufacturer: YAGEO; Manufacturer_Part_Number: CC0402BRNPO9BN6R8; Component_Country_Of_Origin: China; ShowFields: YES; ID: 3881
CN16 = MCD-01129: Connector_RJ45, With Gigabit magnetics Mag and LED, 10pins, 2.54mm, VR, TH, T= 13.84mm; Manufacturer_Part_Number: 48F-01GYDXNL; Manufacturer: YUAN DEAN SCIENTIFIC; Part_Preference: Recommended; Component_Country_Of_Origin: Unknown; ShowFields: YES; ID: 3367
D7 = MCD-00034: Diode, Schottky, 0V53, 1A, 10V, SOD323; Manufacturer: STMICROELECTRONICS; BMS_Part_Number: 9151097; Part_Preference: Recommended; Manufacturer_HQ_COO: EU; Component_Country_Of_Origin: China; ShowFields: YES; ID: 2483; Order_Code_RS: 714-6879
L1 L2 = MCD-00094: Ferrite bead, 100R @ 100MHz, +/-25%, 2000mA, 0R045, 0603, T=0.5mm; Manufacturer_Part_Number: BLM18EG101TN1; Manufacturer: MURATA; Part_Type: Inductor; Part_Preference: Recommended; Order_Code_RS: 1515714; Component_Country_Of_Origin: Japan°°; ShowFields: YES; ID: 2774
LD7 = MCD-00588: as LD6 on sheet Arduino_UNO_R3_SMD
LE1 = MCD-00048: Inductor, 4.7uH, +/-30%, 1A, 180mR, 1210, T=1.7mm; Manufacturer_Part_Number: LQH32PN4R7NN0L; Manufacturer: MURATA; Part_Preference: Recommended; Order_Code_RS: 2470296; Component_Country_Of_Origin: Japan°°; ShowFields: YES; ID: 2544
R6 R9 = MCD-00056: Resistor, 0R, 0603, +/-5%, 1/10W; Manufacturer_Part_Number: RC0603JR-070RL; Manufacturer: YAGEO; Part_Preference: Recommended; Order_Code_RS: 9233130RL; Component_Country_Of_Origin: China; ShowFields: YES; ID: 2536
R13-R18 R174-R178 R191 R194 R195 = MCD-00065: Resistor, 4K7, 0402, +/-1%, 1/16W; Manufacturer_Part_Number: RC0402FR-074K7L; Manufacturer: YAGEO; Part_Preference: Recommended; Partial_Alternate_Internal_Part_Number: MCD-03300; Order_Code_RS: 9239316; Component_Country_Of_Origin: China; ShowFields: YES; ID: 2526
R160-R162 R166 R169 R172 R180-R185 R196 R203 = MCD-00189: Resistor, 22R, 0402, +/-1%, 1/16W; Manufacturer_Part_Number: RC0402FR-0722RL; Manufacturer: YAGEO; Part_Preference: Recommended; Component_Country_Of_Origin: China; ShowFields: YES; ID: 2677
R186 R200 R204 = MCD-00068: Resistor, 1K5, 0402, +/-1%, 1/16W; Manufacturer_Part_Number: RC0402FR-071K5L; Manufacturer: YAGEO; Part_Preference: Recommended; Order_Code_RS: 9239251; Component_Country_Of_Origin: China; ShowFields: YES; ID: 2524
R190 R218 R219 = MCD-00064: Resistor, 510R, 0402, +/-1%, 1/16W; Manufacturer_Part_Number: RC0402FR-07510RL; Manufacturer: YAGEO; Part_Preference: Recommended; Order_Code_RS: 1458804; Component_Country_Of_Origin: China; ShowFields: YES; ID: 2525
R198 R205 = MCD-00052: as R137 on sheet Arduino_UNO_R3_SMD
R207 = MCD-00053: Resistor, 10K, 0402, +/-1%, 1/16W; Manufacturer_Part_Number: RC0402FR-0710KL; Manufacturer: YAGEO; BMS_Part_Number: 9131590; Part_Preference: Recommended; Order_Code_RS: 9239359; Component_Country_Of_Origin: China; ShowFields: YES; ID: 2539
R208 = MCD-00183: Resistor, 2K49, 0402, +/-1%, 1/16W; Manufacturer_Part_Number: RC0402FR-072K49L; Manufacturer: YAGEO; Part_Preference: Recommended; Component_Country_Of_Origin: China; ShowFields: YES; ID: 2687
SB3 = MCD-01618: Resistor, 0R, SB0402, 5%, 0.063W; Manufacturer_Part_Number: RC0402JR-070RL; Manufacturer: YAGEO; Part_Preference: Recommended; Order_Code_RS: 618-5804; Component_Country_Of_Origin: China; ShowFields: YES; ID: 3718
U44 = MCD-01130: ETHERNET Transceiver, 10/100/1000M, QFN40 , SMPS version; Manufacturer: REALTEK; Part_Type: IC; Part_Preference: Recommended; Component_Country_Of_Origin: USA; ShowFields: YES; ID: 3370
X4 = MCD-01463: Crystal, 25MHz, 10pF, +/-20ppm, 50R, 3.2x2.5mm; Part_Type: Crystal_Osc; Manufacturer_Part_Number: NX3225GA-25MHZ-EXS00A-CG06750; Manufacturer: NDK; BMS_Part_Number: 9157035; Part_Preference: Recommended; Component_Country_Of_Origin: Unknown; ShowFields: YES; ID: 3563

## Sheet External_Debug_Interface.SchDoc: External_Debug_Interface
size A4; Date: Not used; ApprovedBy: Not used; CheckedBy: Not used; Author: Not used; CompanyName: STMicroelectronics; DrawnBy: Not used; Engineer: Not used; Organization: Not used; Address1: Not used; Address2: Not used; Address3: Not used; Address4: Not used; DocumentNumber: Not used; Revision: V0.1; SheetNumber: 20; SheetTotal: 21
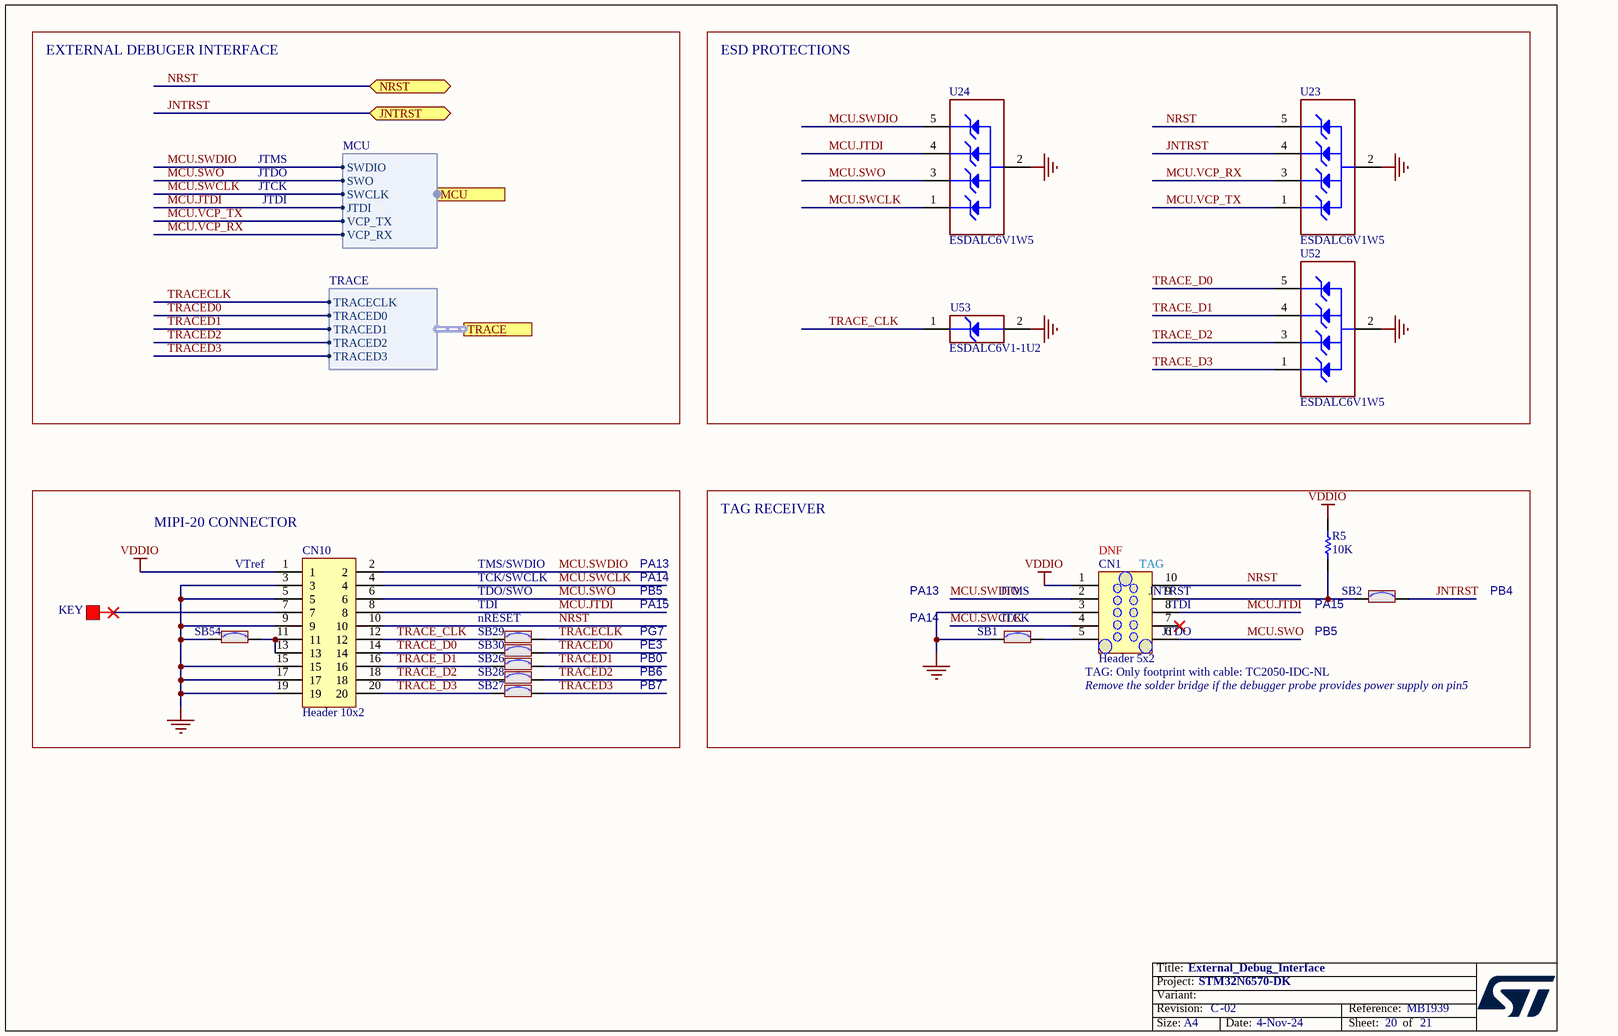
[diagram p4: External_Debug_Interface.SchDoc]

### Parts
CN1  value Header 5x2  [CON_TAG-C_TC2050-IDC-NL]  (hidden comment: Tag-10-C)  (no BOM)
CN10  Header 10x2  [CON_SAMTEC_FTSH-110-01-L-DV]
R5  value 10K  [R0402]  (hidden comment: Resistor)
SB1  SB_ON  [SOLDER-BRIDGE_R0603-0R]  (value not drawn)
SB2  SB_ON  [SOLDER-BRIDGE_R0603-0R]  (value not drawn)
SB26  SB_ON  [SOLDER-BRIDGE_R0402-0R]  (value not drawn)
SB27  SB_ON  [SOLDER-BRIDGE_R0402-0R]  (value not drawn)
SB28  SB_ON  [SOLDER-BRIDGE_R0402-0R]  (value not drawn)
SB29  SB_ON  [SOLDER-BRIDGE_R0402-0R]  (value not drawn)
SB30  SB_ON  [SOLDER-BRIDGE_R0402-0R]  (value not drawn)
SB54  SB_ON  [SOLDER-BRIDGE_R0402-0R]  (value not drawn)
U23  ESDALC6V1W5  [ESD_SOT323-5L]
U24  ESDALC6V1W5  [ESD_SOT323-5L]
U52  ESDALC6V1W5  [ESD_SOT323-5L]
U53  value ESDALC6V1-1U2  [ESD_ST0201]  (hidden comment: ESD-TRANSIL)

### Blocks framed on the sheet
ESD PROTECTIONS: U23 U24 U52 U53
MIPI-20 CONNECTOR: CN10 SB26-SB30 SB54
TAG RECEIVER: CN1 R5 SB1 SB2

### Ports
JNTRST (bidir), MCU (harness MCU), NRST (bidir), TRACE (harness TRACE)

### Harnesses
MCU: SWDIO, SWO, VCP_TX, SWCLK, VCP_RX, JTDI
TRACE: TRACECLK, TRACED2, TRACED0, TRACED3, TRACED1

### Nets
GND: CN1.3 CN10.3 CN10.5 CN10.9 CN10.15 CN10.17 CN10.19 SB1.1 SB54.1 U23.2(GND) U24.2(GND) U52.2(GND) U53.2(GND)
VDDIO: CN1.1 CN10.1 R5.2
JNTRST: SB2.2 U23.4(IO3) ; port JNTRST
MCU.JTDI: CN1.8 CN10.8 U24.4(IO3) ; port MCU.JTDI
MCU.SWCLK: CN1.4 CN10.4 U24.1(IO1) ; port MCU.SWCLK
MCU.SWDIO: CN1.2 CN10.2 U24.5(IO4) ; port MCU.SWDIO
MCU.SWO: CN1.6 CN10.6 U24.3(IO2) ; port MCU.SWO
MCU.VCP_RX: U23.3(IO2) ; port MCU.VCP_RX
MCU.VCP_TX: U23.1(IO1) ; port MCU.VCP_TX
NRST: CN1.10 CN10.10 U23.5(IO4) ; port NRST
TRACE_CLK: CN10.12 SB29.1 U53.1(IO1)
TRACE_D0: CN10.14 SB30.1 U52.5(IO4)
TRACE_D1: CN10.16 SB26.1 U52.4(IO3)
TRACE_D2: CN10.18 SB28.1 U52.3(IO2)
TRACE_D3: CN10.20 SB27.1 U52.1(IO1)
TRACECLK: SB29.2 ; port TRACE.TRACECLK  [project net PG7]
TRACED0: SB30.2 ; port TRACE.TRACED0  [project net PE3]
TRACED1: SB26.2 ; port TRACE.TRACED1  [project net PB0]
TRACED2: SB28.2 ; port TRACE.TRACED2  [project net PB6]
TRACED3: SB27.2 ; port TRACE.TRACED3  [project net PB7]
NetCN1_5: CN1.5 SB1.2
NetCN1_9: CN1.9 R5.1 SB2.1
NetCN10_11: CN10.11 CN10.13 SB54.2

Not connected (* = marked no-connect by the designer): CN1 7*; CN10 7*

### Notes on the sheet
- EXTERNAL DEBUGER INTERFACE
- JTMS
- JTDO
- JTCK
- JTDI
- (near CN10) VTref
- TMS/SWDIO
- TCK/SWCLK
- PA13
- PA14
- (near CN1) DNF
- (near CN1) TAG
- KEY
- TDO/SWO
- TDI
- (near SB29) nRESET
- PG7
- PE3
- PA15
- PB5
- (near SB1) JTCK
- (near CN1) JTDO
- (near CN1) JTDI
- (near CN1) JNTRST
- PB4
- PB6
- PB0
- PB7
- (near CN1) TAG: Only footprint with cable: TC2050-IDC-NL
- (near CN1) Remove the solder bridge if the debugger probe provides power supply on pin5

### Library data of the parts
CN1 = MCD-00031: Header_Plug-of-nails, 5x2, 1.27mm, No legs; Part_Type: Connector; Part_Preference: Recommended; ShowFields: YES; ID: 2486
CN10 = MCD-00557: Header, 10x2, 1.27mm, VR, SMD, T=3.05mm; BMS_Part_Number: 9183690; Part_Type: Connector; Part_Preference: Recommended; Manufacturer: SAMTEC; Manufacturer_Part_Number: FTSH-110-01-L-DV; Partial_Alternate_Internal_Part_Number: MCD-03996; Order_Code_RS: 767-6774; Component_Country_Of_Origin: China, Costa Rica, Malaysia, USA, Vietnam; ShowFields: YES; ID: 3188
R5 = MCD-00053: as R207 on sheet Ethernet
SB1 SB2 = MCD-00071: Resistor, 0R, SB0603, 5%, 0.1W; Part_Preference: Recommended; Manufacturer: YAGEO; Manufacturer_Part_Number: RC0603JR-070RL; Manufacturer_HQ_COO: Unknown; ShowFields: YES; ID: 2521; Order_Code_RS: 199-5647; Component_Country_Of_Origin: China
SB26-SB30 SB54 = MCD-01618: Resistor, 0R, SB0402, 5%, 0.063W; Part_Preference: Recommended; Manufacturer: YAGEO; Manufacturer_Part_Number: RC0402JR-070RL; ShowFields: YES; ID: 3718; Order_Code_RS: 618-5804; Component_Country_Of_Origin: China
U23 U24 U52 = MCD-00136: Diode, ESD Transil, 3V, 1uA, 7V2, SOT323-5; BMS_Part_Number: 9151112; Part_Preference: Recommended; Manufacturer: STMICROELECTRONICS; Manufacturer_HQ_COO: EU; Component_Country_Of_Origin: China; Order_Code_RS: 178-7373; ShowFields: YES; ID: 2731
U53 = MCD-00170: Diode, ESD TVS, 3V, 100nA, 8V, ST0201; BMS_Part_Number: 9151132; Part_Preference: Recommended; Manufacturer: STMICROELECTRONICS; Manufacturer_HQ_COO: EU; Component_Country_Of_Origin: China; ShowFields: YES; ID: 2696; Order_Code_RS: 795-8404

## Sheet HexaSPI_PSRAM.SchDoc: HexaSPI_PSRAM
size A4; Date: Not used; ApprovedBy: Not used; CheckedBy: Not used; Author: Not used; CompanyName: STMicroelectronics; DrawnBy: Not used; Engineer: Not used; Organization: Not used; Address1: Not used; Address2: Not used; Address3: Not used; Address4: Not used; DocumentNumber: Not used; Revision: Not used; SheetNumber: 6; SheetTotal: 21
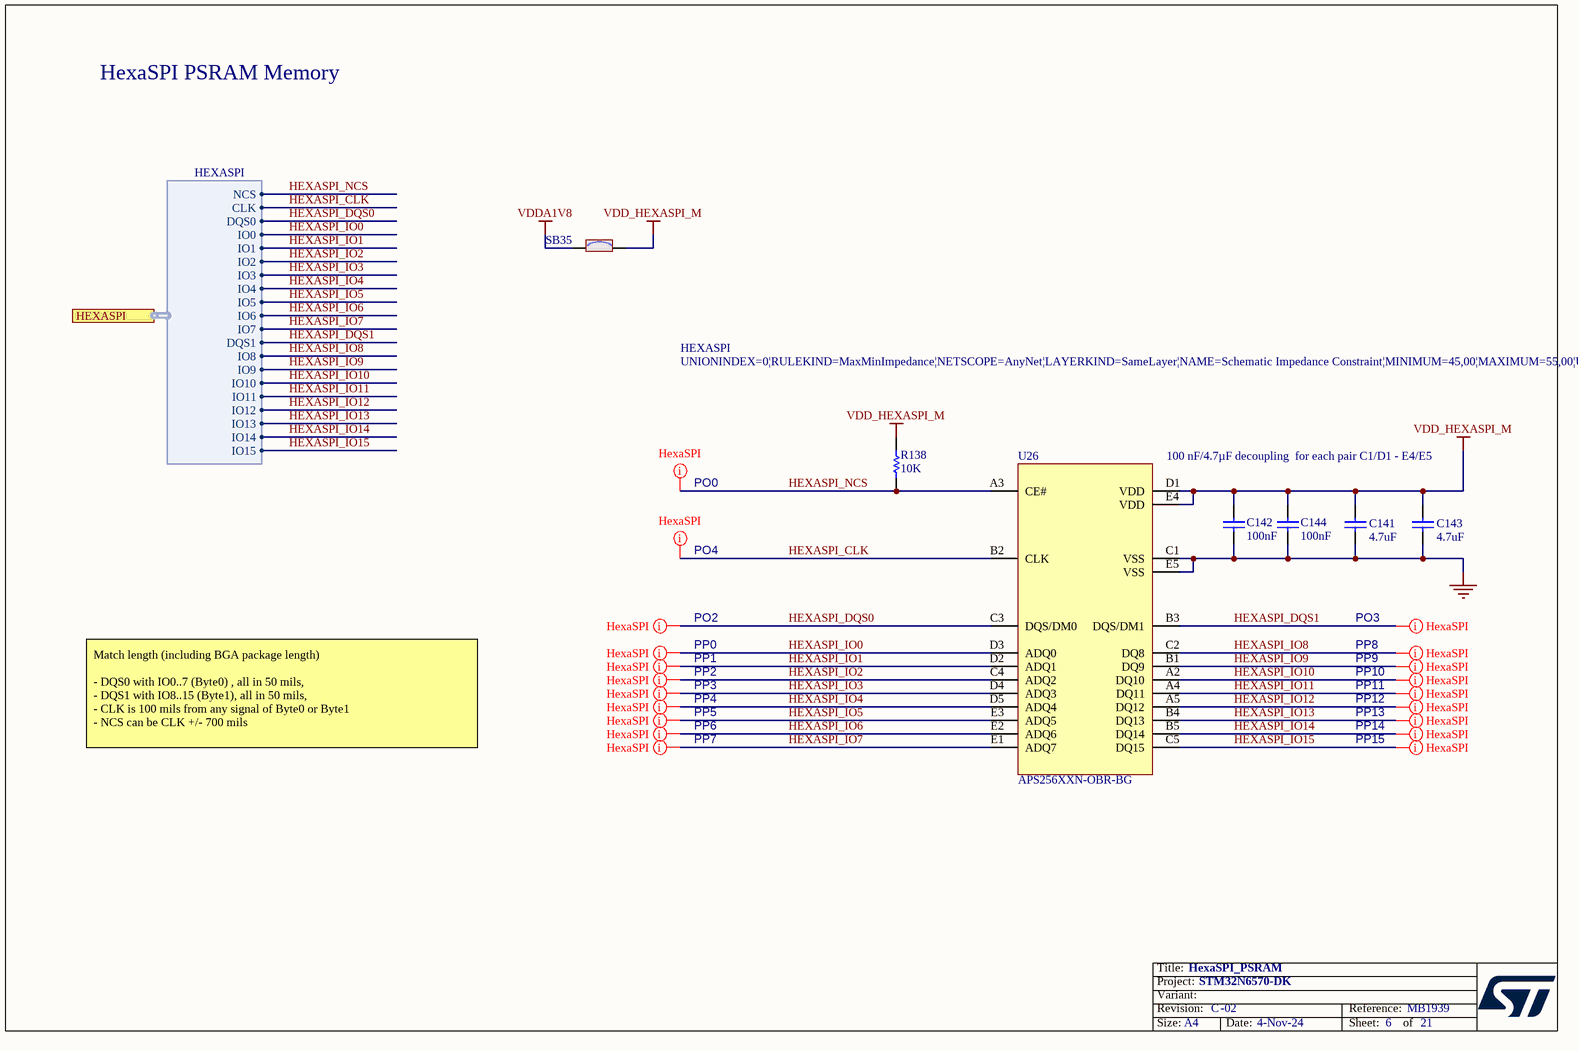
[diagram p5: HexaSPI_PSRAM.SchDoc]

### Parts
C141  value 4.7uF  [C0603]  (hidden comment: Capacitor)
C142  value 100nF  [C0402]  (hidden comment: Capacitor)
C143  value 4.7uF  [C0603]  (hidden comment: Capacitor)
C144  value 100nF  [C0402]  (hidden comment: Capacitor)
R138  value 10K  [R0402]  (hidden comment: Resistor)
SB35  SB_ON  [SOLDER-BRIDGE_R0402-0R]  (value not drawn)
U26  APS256XXN-OBR-BG  [ICC_BGA24_5X5-BALL-ARRAY_6X8_P1]

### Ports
HEXASPI (harness HEXASPI)

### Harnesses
HEXASPI: IO1, IO0, DQS0, NCS, IO2, IO3, IO5, IO4, IO6, IO7, CLK, DQS1, IO8, IO9, IO10, IO11, IO12, IO13, IO14, IO15

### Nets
GND: C141.1 C142.1 C143.1 C144.1 U26.C1(VSS) U26.E5(VSS)
VDD_HEXASPI_M: C141.2 C142.2 C143.2 C144.2 R138.2 SB35.2 U26.D1(VDD) U26.E4(VDD)
VDDA1V8: SB35.1
HEXASPI_CLK: U26.B2(CLK) ; port HEXASPI.CLK
HEXASPI_DQS0: U26.C3(DQS/DM0) ; port HEXASPI.DQS0
HEXASPI_DQS1: U26.B3(DQS/DM1) ; port HEXASPI.DQS1
HEXASPI_IO0: U26.D3(ADQ0) ; port HEXASPI.IO0
HEXASPI_IO1: U26.D2(ADQ1) ; port HEXASPI.IO1
HEXASPI_IO2: U26.C4(ADQ2) ; port HEXASPI.IO2
HEXASPI_IO3: U26.D4(ADQ3) ; port HEXASPI.IO3
HEXASPI_IO4: U26.D5(ADQ4) ; port HEXASPI.IO4
HEXASPI_IO5: U26.E3(ADQ5) ; port HEXASPI.IO5
HEXASPI_IO6: U26.E2(ADQ6) ; port HEXASPI.IO6
HEXASPI_IO7: U26.E1(ADQ7) ; port HEXASPI.IO7
HEXASPI_IO8: U26.C2(DQ8) ; port HEXASPI.IO8
HEXASPI_IO9: U26.B1(DQ9) ; port HEXASPI.IO9
HEXASPI_IO10: U26.A2(DQ10) ; port HEXASPI.IO10
HEXASPI_IO11: U26.A4(DQ11) ; port HEXASPI.IO11
HEXASPI_IO12: U26.A5(DQ12) ; port HEXASPI.IO12
HEXASPI_IO13: U26.B4(DQ13) ; port HEXASPI.IO13
HEXASPI_IO14: U26.B5(DQ14) ; port HEXASPI.IO14
HEXASPI_IO15: U26.C5(DQ15) ; port HEXASPI.IO15
HEXASPI_NCS: R138.1 U26.A3(CE#) ; port HEXASPI.NCS

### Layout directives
rule Matched Net Lengths [Tolerance = 1000mil]; net class HEXASPI; rule Impedance Constraint [Min = 50.00    Max = 60.00    ]; rule Routing Layers [TopLayer - Enabled BottomLayer - Disabled]: HEXASPI_NCS
rule Matched Net Lengths [Tolerance = 20mil]; net class HEXASPI; rule Impedance Constraint [Min = 45.00    Max = 55.00    ]; rule Routing Layers [TopLayer - Enabled BottomLayer - Disabled]: HEXASPI_CLK, HEXASPI_DQS1, HEXASPI_IO0, HEXASPI_IO1, HEXASPI_IO2, HEXASPI_IO3, HEXASPI_IO4, HEXASPI_IO5, HEXASPI_IO6, HEXASPI_IO7, HEXASPI_IO8, HEXASPI_IO9, HEXASPI_IO10, HEXASPI_IO11, HEXASPI_IO12, HEXASPI_IO13, HEXASPI_IO14, HEXASPI_IO15
rule Matched Net Lengths [Tolerance = 20mil]; net class HEXASPI; rule Impedance Constraint [Min = 50.00    Max = 60.00    ]; rule Routing Layers [TopLayer - Enabled BottomLayer - Disabled]: HEXASPI_DQS0

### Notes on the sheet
- HexaSPI PSRAM Memory
- PO0
- (near U26) 100 nF/4.7µF decoupling  for each pair C1/D1 - E4/E5
- PO4
- PO2
- PP0
- PO3
- PP8
- PP1
- PP2
- PP3
- PP4
- PP5
- PP9
- PP10
- PP11
- PP12
- PP13
- Match length (including BGA package length)
  - DQS0 with IO0..7 (Byte0) , all in 50 mils,
  - DQS1 with IO8..15 (Byte1), all in 50 mils,
  - CLK is 100 mils from any signal of Byte0 or Byte1
  - NCS can be CLK +/- 700 mils
- PP6
- PP7
- PP14
- PP15
- Title:
- Project:
- Size:
- Revision:
- Variant:
- A4
- -
- Date:
- Reference:
- Sheet:
- of

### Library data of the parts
C141 C143 = MCD-00009: Capacitor, MLCC, 4.7uF, 16V, X5R, +/-10%, 0603, T=0.8mm; Manufacturer_Part_Number: CC0603KRX5R7BB475; Manufacturer: YAGEO; Part_Preference: Recommended; Partial_Alternate_Internal_Part_Number: MCD-03565; Component_Country_Of_Origin: China; ShowFields: YES; ID: 2471; Alternate_EMS: A
C142 C144 = MCD-00006: as C140 on sheet Arduino_UNO_R3_SMD
R138 = MCD-00053: as R207 on sheet Ethernet
SB35 = MCD-01618: as SB3 on sheet Ethernet
U26 = MCD-02129: Memory, DDR PSRAM, 1V8, 256Mbit, 200MHz, BGA-24; Part_Type: IC; Manufacturer: AP MEMORY TECHNOLOGY CORP.; Part_Preference: Recommended; Component_Country_Of_Origin: Taiwan; ShowFields: YES; ID: 4229

## Sheet LCD.SchDoc: LCD & Camera connectors
size A4; Date: Not used; ApprovedBy: Not used; CheckedBy: Not used; Author: Not used; CompanyName: STMicroelectronics; DrawnBy: Not used; Engineer: Not used; Organization: Not used; Address1: Not used; Address2: Not used; Address3: Not used; Address4: Not used; DocumentNumber: Not used; Revision: Not used; SheetNumber: 11; SheetTotal: 21
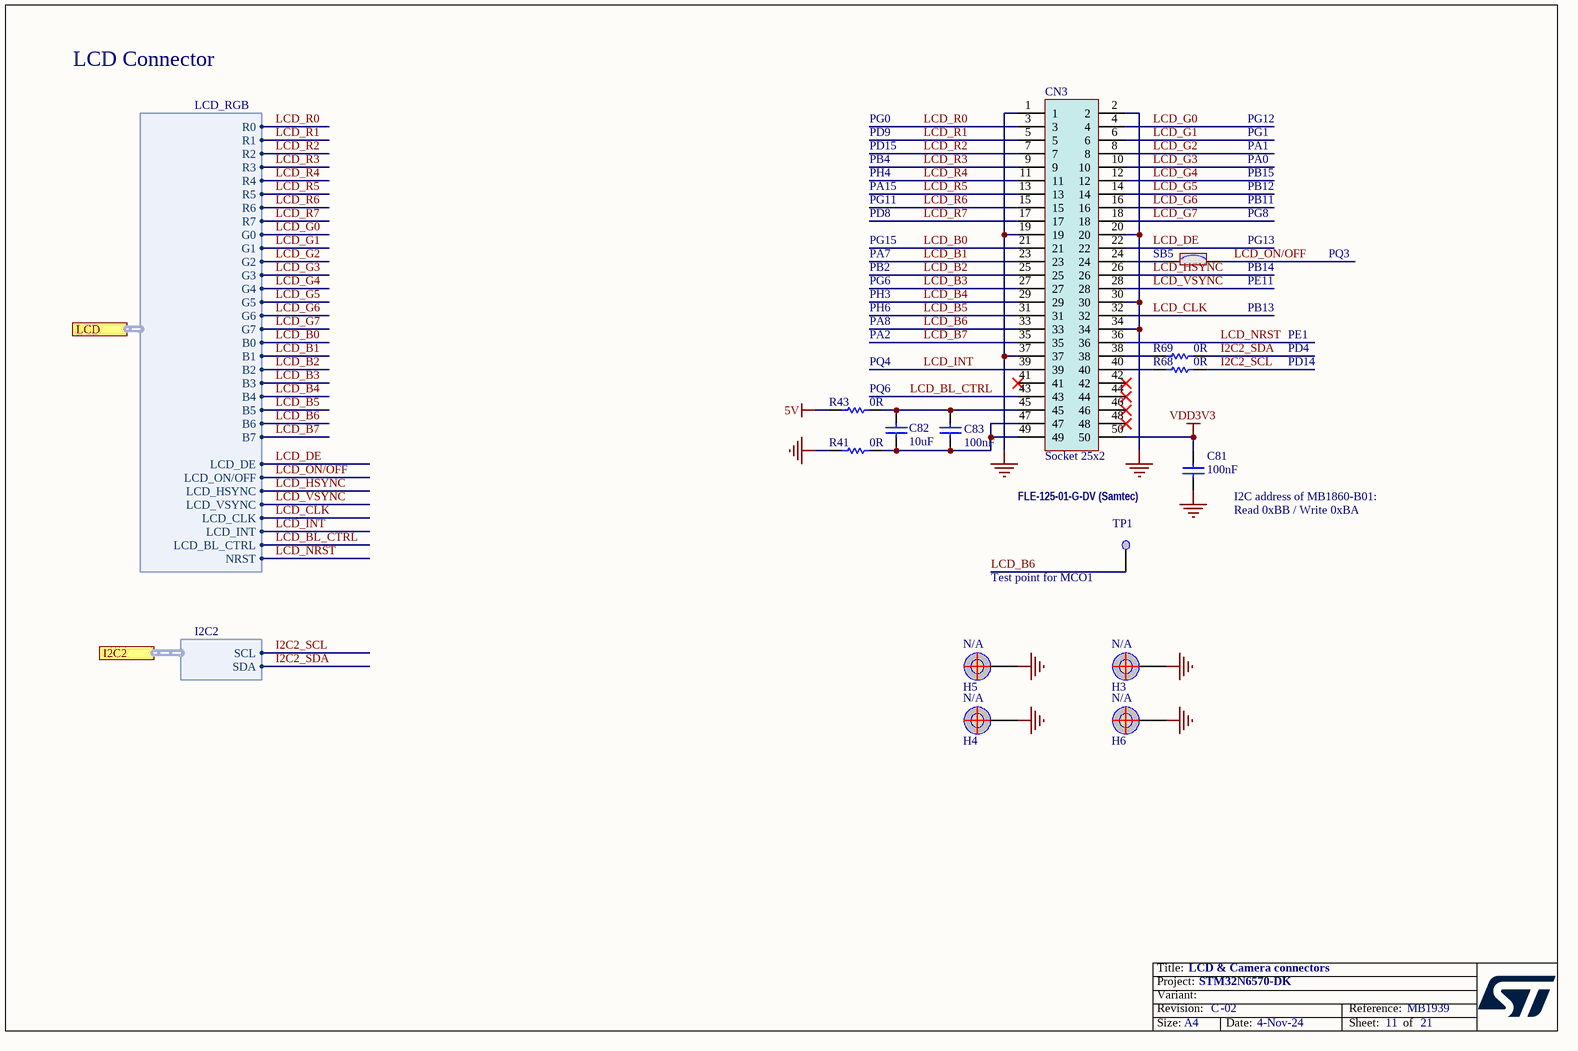
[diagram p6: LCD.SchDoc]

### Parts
C81  value 100nF  [C0402]  (hidden comment: Capacitor)
C82  value 10uF  [C0805]  (hidden comment: Capacitor)
C83  value 100nF  [C0402]  (hidden comment: Capacitor)
CN3  Socket 25x2  [CON_SAMTEC_FLE-125-01-G-DV]
H3  POSITION HOLE  [PTH_450_900]  (value not drawn)  (no BOM)
H4  POSITION HOLE  [PTH_450_900]  (value not drawn)  (no BOM)
H5  POSITION HOLE  [PTH_450_900]  (value not drawn)  (no BOM)
H6  POSITION HOLE  [PTH_450_900]  (value not drawn)  (no BOM)
R41  value 0R  [R0603]  (hidden comment: Resistor)
R43  value 0R  [R0603]  (hidden comment: Resistor)
R68  value 0R  [R0402]  (hidden comment: Resistor)
R69  value 0R  [R0402]  (hidden comment: Resistor)
SB5  SB_ON  [SOLDER-BRIDGE_R0603-0R]  (value not drawn)
TP1  Test Point  [TP_SMD_2MM]  (value not drawn)  (no BOM)

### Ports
I2C2 (harness I2C2), LCD (harness LCD_RGB)

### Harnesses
I2C2: SCL, SDA
LCD_RGB: R0, R1, G0, B0, R2, R3, R4, R5, R6, R7, G1, G2, G3, G4, G5, G6, G7, B1, B2, B3, B4, B5, B6, B7, LCD_DE, LCD_ON/OFF, LCD_HSYNC, LCD_VSYNC, LCD_CLK, LCD_INT, LCD_BL_CTRL, NRST

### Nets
5V: R43.1
GND: C81.2 CN3.1 CN3.2 CN3.19 CN3.20 CN3.30 CN3.34 CN3.37 H3.1 H4.1 H5.1 H6.1 R41.1
VDD3V3: C81.1 CN3.50
I2C2_SCL: R68.2 ; port I2C2.SCL
I2C2_SDA: R69.2 ; port I2C2.SDA
LCD_B0: CN3.21 ; port LCD.B0
LCD_B1: CN3.23 ; port LCD.B1
LCD_B2: CN3.25 ; port LCD.B2
LCD_B3: CN3.27 ; port LCD.B3
LCD_B4: CN3.29 ; port LCD.B4
LCD_B5: CN3.31 ; port LCD.B5
LCD_B6: CN3.33 TP1.1 ; port LCD.B6
LCD_B7: CN3.35 ; port LCD.B7
LCD_BL_CTRL: CN3.43 ; port LCD.LCD_BL_CTRL
LCD_CLK: CN3.32 ; port LCD.LCD_CLK
LCD_DE: CN3.22 ; port LCD.LCD_DE
LCD_G0: CN3.4 ; port LCD.G0
LCD_G1: CN3.6 ; port LCD.G1
LCD_G2: CN3.8 ; port LCD.G2
LCD_G3: CN3.10 ; port LCD.G3
LCD_G4: CN3.12 ; port LCD.G4
LCD_G5: CN3.14 ; port LCD.G5
LCD_G6: CN3.16 ; port LCD.G6
LCD_G7: CN3.18 ; port LCD.G7
LCD_HSYNC: CN3.26 ; port LCD.LCD_HSYNC
LCD_INT: CN3.39 ; port LCD.LCD_INT
LCD_NRST: CN3.36 ; port LCD.NRST
LCD_ON/OFF: SB5.2 ; port LCD.LCD_ON/OFF
LCD_R0: CN3.3 ; port LCD.R0
LCD_R1: CN3.5 ; port LCD.R1
LCD_R2: CN3.7 ; port LCD.R2
LCD_R3: CN3.9 ; port LCD.R3
LCD_R4: CN3.11 ; port LCD.R4
LCD_R5: CN3.13 ; port LCD.R5
LCD_R6: CN3.15 ; port LCD.R6
LCD_R7: CN3.17 ; port LCD.R7
LCD_VSYNC: CN3.28 ; port LCD.LCD_VSYNC
NetC82_1: C82.1 C83.2 CN3.47 CN3.49 R41.2
NetC82_2: C82.2 C83.1 CN3.45 R43.2
NetCN3_24: CN3.24 SB5.1
NetCN3_38: CN3.38 R69.1
NetCN3_40: CN3.40 R68.1

Not connected (* = marked no-connect by the designer): CN3 41* 42* 44* 46* 48*

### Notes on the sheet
- LCD Connector
- PG0
- PD9
- PD15
- PB4
- PH4
- PG12
- PG1
- PA1
- PA0
- PB15
- PA15
- PG11
- PD8
- PG15
- PB12
- PB11
- PG8
- (near SB5) PG13
- PH6
- PH3
- PG6
- PB2
- PA7
- (near SB5) PB14
- PB13
- (near SB5) PE11
- PQ3
- PA8
- PA2
- PQ4
- PE1
- PD4
- PD14
- (near R43) PQ6
- FLE-125-01-G-DV (Samtec)
- (near C81) I2C address of MB1860-B01:
- (near C81) Read 0xBB / Write 0xBA
- (near TP1) Test point for MCO1
- Title:
- Project:
- Size:
- Revision:
- Variant:
- A4
- -
- Date:
- Reference:
- Sheet:
- of

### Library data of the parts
C81 C83 = MCD-00006: as C140 on sheet Arduino_UNO_R3_SMD
C82 = MCD-00014: Capacitor, MLCC, 10uF, 25V, X5R, +/-10%, 0805, T=0.85mm; Manufacturer_Part_Number: CC0805KRX5R8BB106; Manufacturer: YAGEO; Part_Preference: Recommended; Full_Alternate_Internal_Part_Number: MCD-02385; Partial_Alternate_Internal_Part_Number: MCD-03053; Component_Country_Of_Origin: China; ShowFields: YES; ID: 2468
CN3 = MCD-01222: Socket, 25x2, 1.27mm, SMD, VR, T=4.55mm; Part_Type: Connector; Manufacturer_Part_Number: FLE-125-01-G-DV; Manufacturer: SAMTEC; Part_Preference: Recommended; Partial_Alternate_Internal_Part_Number: MCD-03153; Order_Code_RS: 766-8965; Component_Country_Of_Origin: China, Costa Rica, Malaysia, USA, Vietnam; ShowFields: YES; ID: 3274
H3-H6 = MCD-01612: POSITION HOLE, C9D4R5; Part_Type: Mechanical; Part_Preference: Recommended; ShowFields: YES; ID: 3712; Component_Country_Of_Origin: Unknown
R41 R43 = MCD-00056: as R6 on sheet Ethernet
R68 R69 = MCD-00052: as R137 on sheet Arduino_UNO_R3_SMD
SB5 = MCD-00071: as SB1 on sheet External_Debug_Interface
TP1 = MCD-00177: as TP5 on sheet Arduino_UNO_R3_SMD

## Sheet Peripherals.SchDoc: Schematic sheet title to update
size A4; Date: Not used; ApprovedBy: Not used; CheckedBy: Not used; Author: Not used; CompanyName: STMicroelectronics; DrawnBy: Not used; Engineer: Not used; Organization: Not used; Address1: Not used; Address2: Not used; Address3: Not used; Address4: Not used; DocumentNumber: Not used; Revision: Not used; SheetNumber: 8; SheetTotal: 21
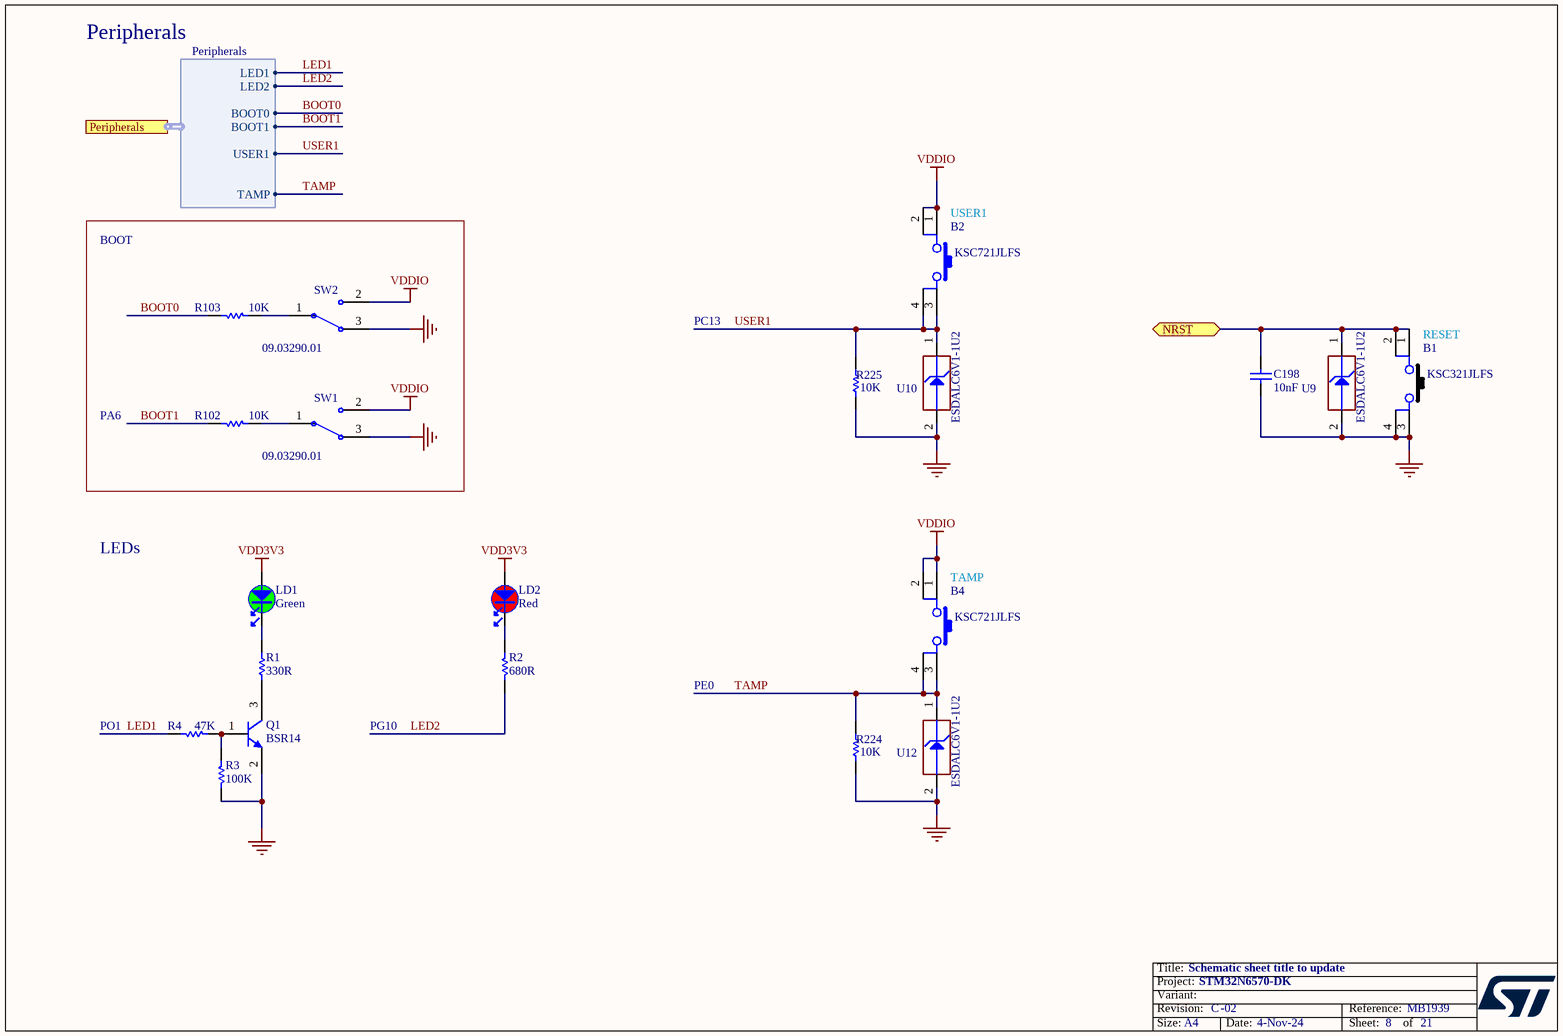
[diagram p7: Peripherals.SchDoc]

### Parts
B1  value KSC321JLFS  [SWI_C&K_KSC321JLFS_BLACK]  (hidden comment: SW_BLACK_KSC321JLFS)
B2  value KSC721JLFS  [SWI_C&K_KSC721JLFS_BLUE]  (hidden comment: SW_BLUE_KSC721JLFS)
B4  value KSC721JLFS  [SWI_C&K_KSC721JLFS_BLUE]  (hidden comment: SW_BLUE_KSC721JLFS)
C198  value 10nF  [C0402]  (hidden comment: Capacitor)
LD1  value Green  [LED_0603_OSRAM_LG-Q396-PS-35_GREEN_1A2K_H0P4]  (hidden comment: LED_green)
LD2  value Red  [LED_0603_VISHAY_VLMS1300-GS08_RED_1A2K_H0P8]  (hidden comment: LED_red)
Q1  value BSR14  [NPN_SOT23]  (hidden comment: 9013-SOT23)
R1  value 330R  [R0402]  (hidden comment: Resistor)
R2  value 680R  [R0402]  (hidden comment: Resistor)
R3  value 100K  [R0402]  (hidden comment: Resistor)
R4  value 47K  [R0402]  (hidden comment: Resistor)
R102  value 10K  [R0402]  (hidden comment: Resistor)
R103  value 10K  [R0402]  (hidden comment: Resistor)
R224  value 10K  [R0402]  (hidden comment: Resistor)
R225  value 10K  [R0402]  (hidden comment: Resistor)
SW1  value 09.03290.01  [SWI_EAO_09-03290-01_EXTENDED_STRAIGHT_BLACK]  (hidden comment: SW_MECA_1K2)
SW2  value 09.03290.01  [SWI_EAO_09-03290-01_EXTENDED_STRAIGHT_BLACK]  (hidden comment: SW_MECA_1K2)
U9  value ESDALC6V1-1U2  [ESD_ST0201]  (hidden comment: ESD-TRANSIL)
U10  value ESDALC6V1-1U2  [ESD_ST0201]  (hidden comment: ESD-TRANSIL)
U12  value ESDALC6V1-1U2  [ESD_ST0201]  (hidden comment: ESD-TRANSIL)

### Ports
NRST (bidir), Peripherals (harness Peripherals)

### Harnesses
Peripherals: LED1, LED2, BOOT0, BOOT1, USER1, TAMP

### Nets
GND: B1.3 B1.4 C198.1 Q1.2(E) R3.1 R224.1 R225.1 SW1.3 SW2.3 U9.2(GND) U10.2(GND) U12.2(GND)
VDD3V3: LD1.1 LD2.1
VDDIO: B2.1 B2.2 B4.1 B4.2 SW1.2 SW2.2
BOOT0: R103.2 ; port Peripherals.BOOT0
BOOT1: R102.2 ; port Peripherals.BOOT1
LED1: R4.2 ; port Peripherals.LED1
LED2: R2.1 ; port Peripherals.LED2
NRST: B1.1 B1.2 C198.2 U9.1(IO1) ; port NRST
TAMP: B4.3 B4.4 R224.2 U12.1(IO1) ; port Peripherals.TAMP  [project net PE0]
USER1: B2.3 B2.4 R225.2 U10.1(IO1) ; port Peripherals.USER1  [project net PC13]
NetLD1_2: LD1.2 R1.2
NetLD2_2: LD2.2 R2.2
NetQ1_1: Q1.1(B) R3.2 R4.1
NetQ1_3: Q1.3(C) R1.1
NetR102_1: R102.1 SW1.1
NetR103_1: R103.1 SW2.1

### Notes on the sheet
- Peripherals
- BOOT
- (near B2) USER1
- PC13
- (near B1) RESET
- PA6
- LEDs
- (near B4) TAMP
- PE0
- PO1
- PG10

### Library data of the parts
B1 = MCD-01799: Switch tactile, SPST-NO, 32V, 50mA, 6.2x6.2mm; Part_Type: Misc; Part_Preference: Recommended; Manufacturer: C&K; Manufacturer_HQ_COO: Unknown; Order_Code_RS: 894-9091; Component_Country_Of_Origin: France; ShowFields: YES; ID: 3899
B2 B4 = MCD-01800: Switch tactile, SPST-NO, 32V, 50mA, 6.2x6.2mm; Part_Type: Misc; Part_Preference: Recommended; Manufacturer: C&K; Partial_Alternate_Internal_Part_Number: MCD-03151; Manufacturer_HQ_COO: Unknown; Component_Country_Of_Origin: France; ShowFields: YES; ID: 3900
C198 = MCD-00011: Capacitor, MLCC, 10nF, 16V, X7R, +/-10%, 0402, T=0.5mm; Part_Preference: Recommended; Manufacturer: YAGEO; Manufacturer_Part_Number: CC0402KRX7R7BB103; Order_Code_RS: 3019275; Component_Country_Of_Origin: China; ShowFields: YES; ID: 2469
LD1 = MCD-00588: LED, Green, 2V, 20mA, 0603; Part_Preference: Recommended; Part_Type: Display; Manufacturer: OSRAM OPTO SEMICONDUCTORS; Manufacturer_Part_Number: LG Q396-PS-35; Partial_Alternate_Internal_Part_Number: MCD-02400, MCD-03155, MCD-02901; Component_Country_Of_Origin: Unknown; ShowFields: YES; ID: 3155
LD2 = MCD-00587: LED, Red, 2V, 20mA, 0603; Manufacturer_Part_Number: VLMS1300-GS08; Manufacturer: VISHAY; Part_Type: Display; Part_Preference: Recommended; Full_Alternate_Internal_Part_Number: MCD-02401; Component_Country_Of_Origin: China; ShowFields: YES; ID: 3154
Q1 = MCD-00073: Transistor, NPN, 40V, 800mA, SOT23; Manufacturer: ON SEMICONDUCTOR; Part_Preference: Recommended; Partial_Alternate_Internal_Part_Number: MCD-01737, MCD-03305, , MCD-02988; Component_Country_Of_Origin: Unknown; ShowFields: YES; ID: 2519
R1 = MCD-00062: as R131 on sheet Arduino_UNO_R3_SMD
R2 = MCD-00507: Resistor, 680R, 0402, +/-1%, 1/16W; Part_Preference: Recommended; Manufacturer: YAGEO; Manufacturer_Part_Number: RC0402FR-07680RL; Component_Country_Of_Origin: China; ShowFields: YES; ID: 3238
R3 = MCD-00059: Resistor, 100K, 0402, +/-1%, 1/16W; Part_Preference: Recommended; Manufacturer: YAGEO; Manufacturer_Part_Number: RC0402FR-07100KL; Partial_Alternate_Internal_Part_Number: MCD-03301; Order_Code_RS: 2421891; Component_Country_Of_Origin: China; ShowFields: YES; ID: 2533
R4 = MCD-00063: Resistor, 47K, 0402, +/-1%, 1/16W; Manufacturer_Part_Number: RC0402FR-0747KL; Manufacturer: YAGEO; Part_Preference: Recommended; Order_Code_RS: 9239430; Component_Country_Of_Origin: China; ShowFields: YES; ID: 2528
R102 R103 R224 R225 = MCD-00053: as R207 on sheet Ethernet
SW1 SW2 = MCD-00566: Switch slide, SPDT, 24V, 500mA, 2.5x10mm; Part_Type: Misc; Part_Preference: Recommended; Manufacturer: EAO; Manufacturer_HQ_COO: Unknown; Component_Country_Of_Origin: Switzerland°°; ShowFields: YES; ID: 3181; Order_Code_RS: 204-7865
U9 U10 U12 = MCD-00170: Diode, ESD TVS, 3V, 100nA, 8V, ST0201; Manufacturer: STMICROELECTRONICS; BMS_Part_Number: 9151132; Part_Preference: Recommended; Manufacturer_HQ_COO: EU; Component_Country_Of_Origin: China; ID: 2696; ShowFields: YES; Order_Code_RS: 795-8404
